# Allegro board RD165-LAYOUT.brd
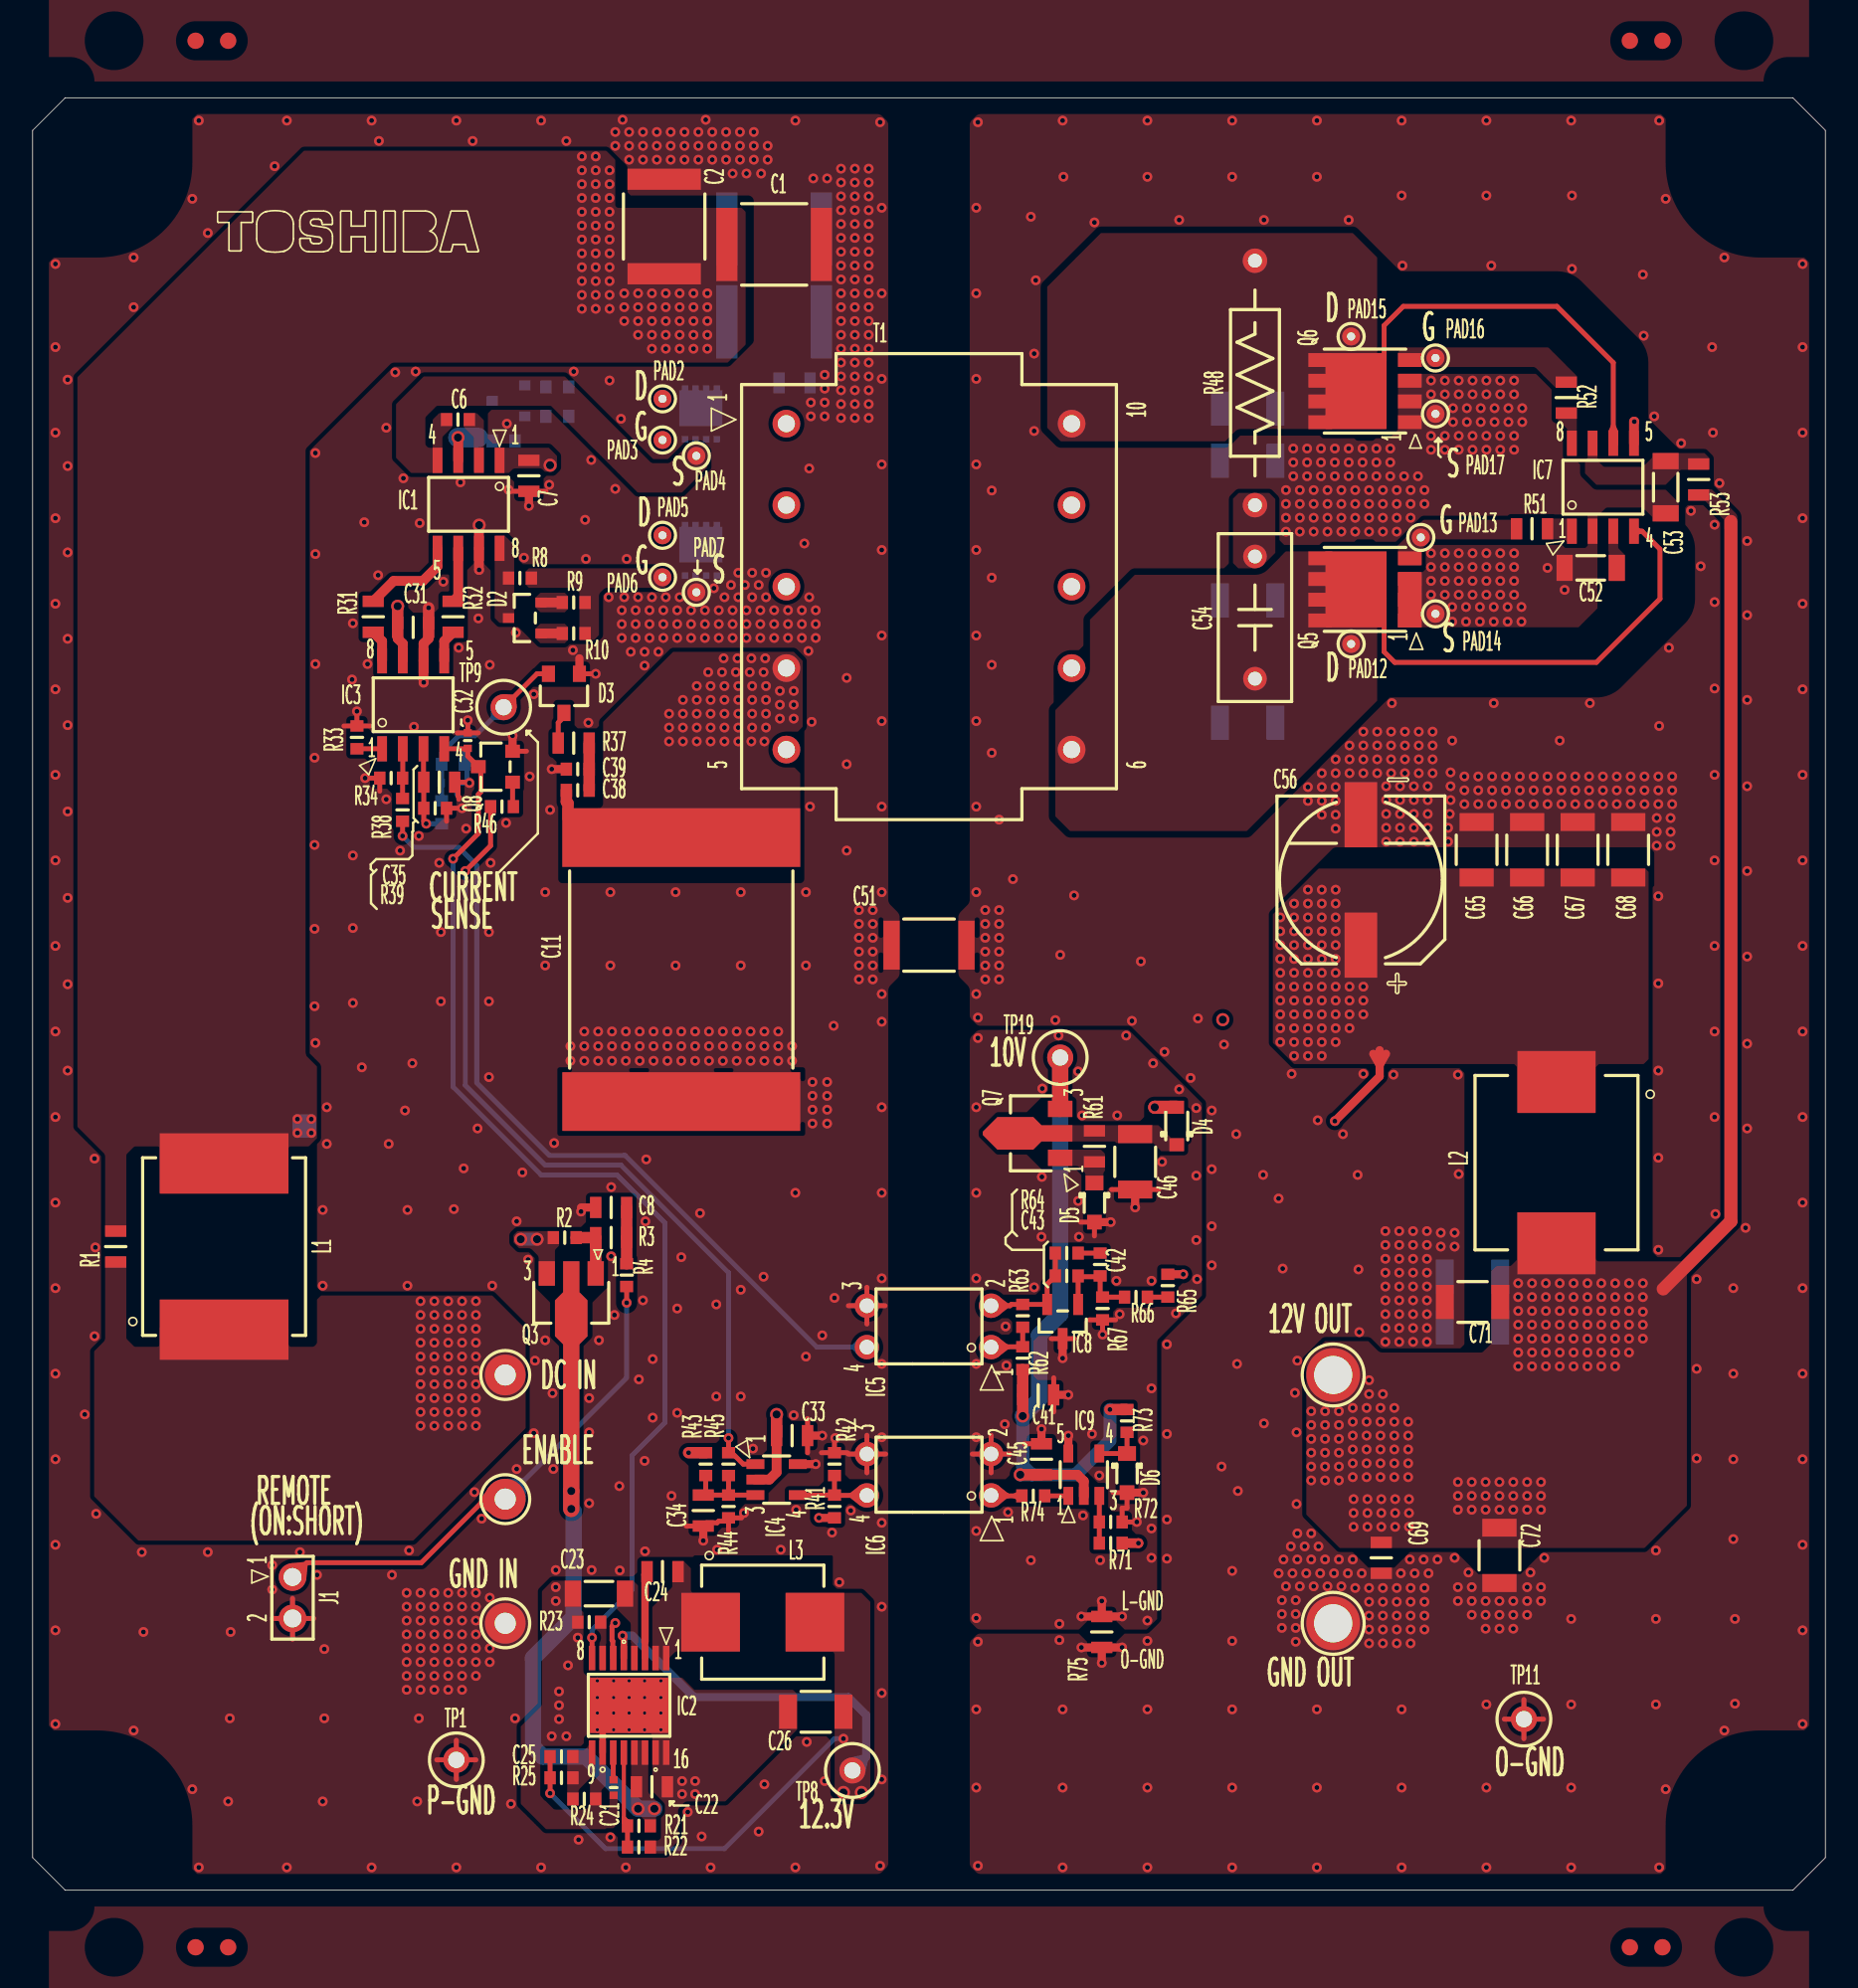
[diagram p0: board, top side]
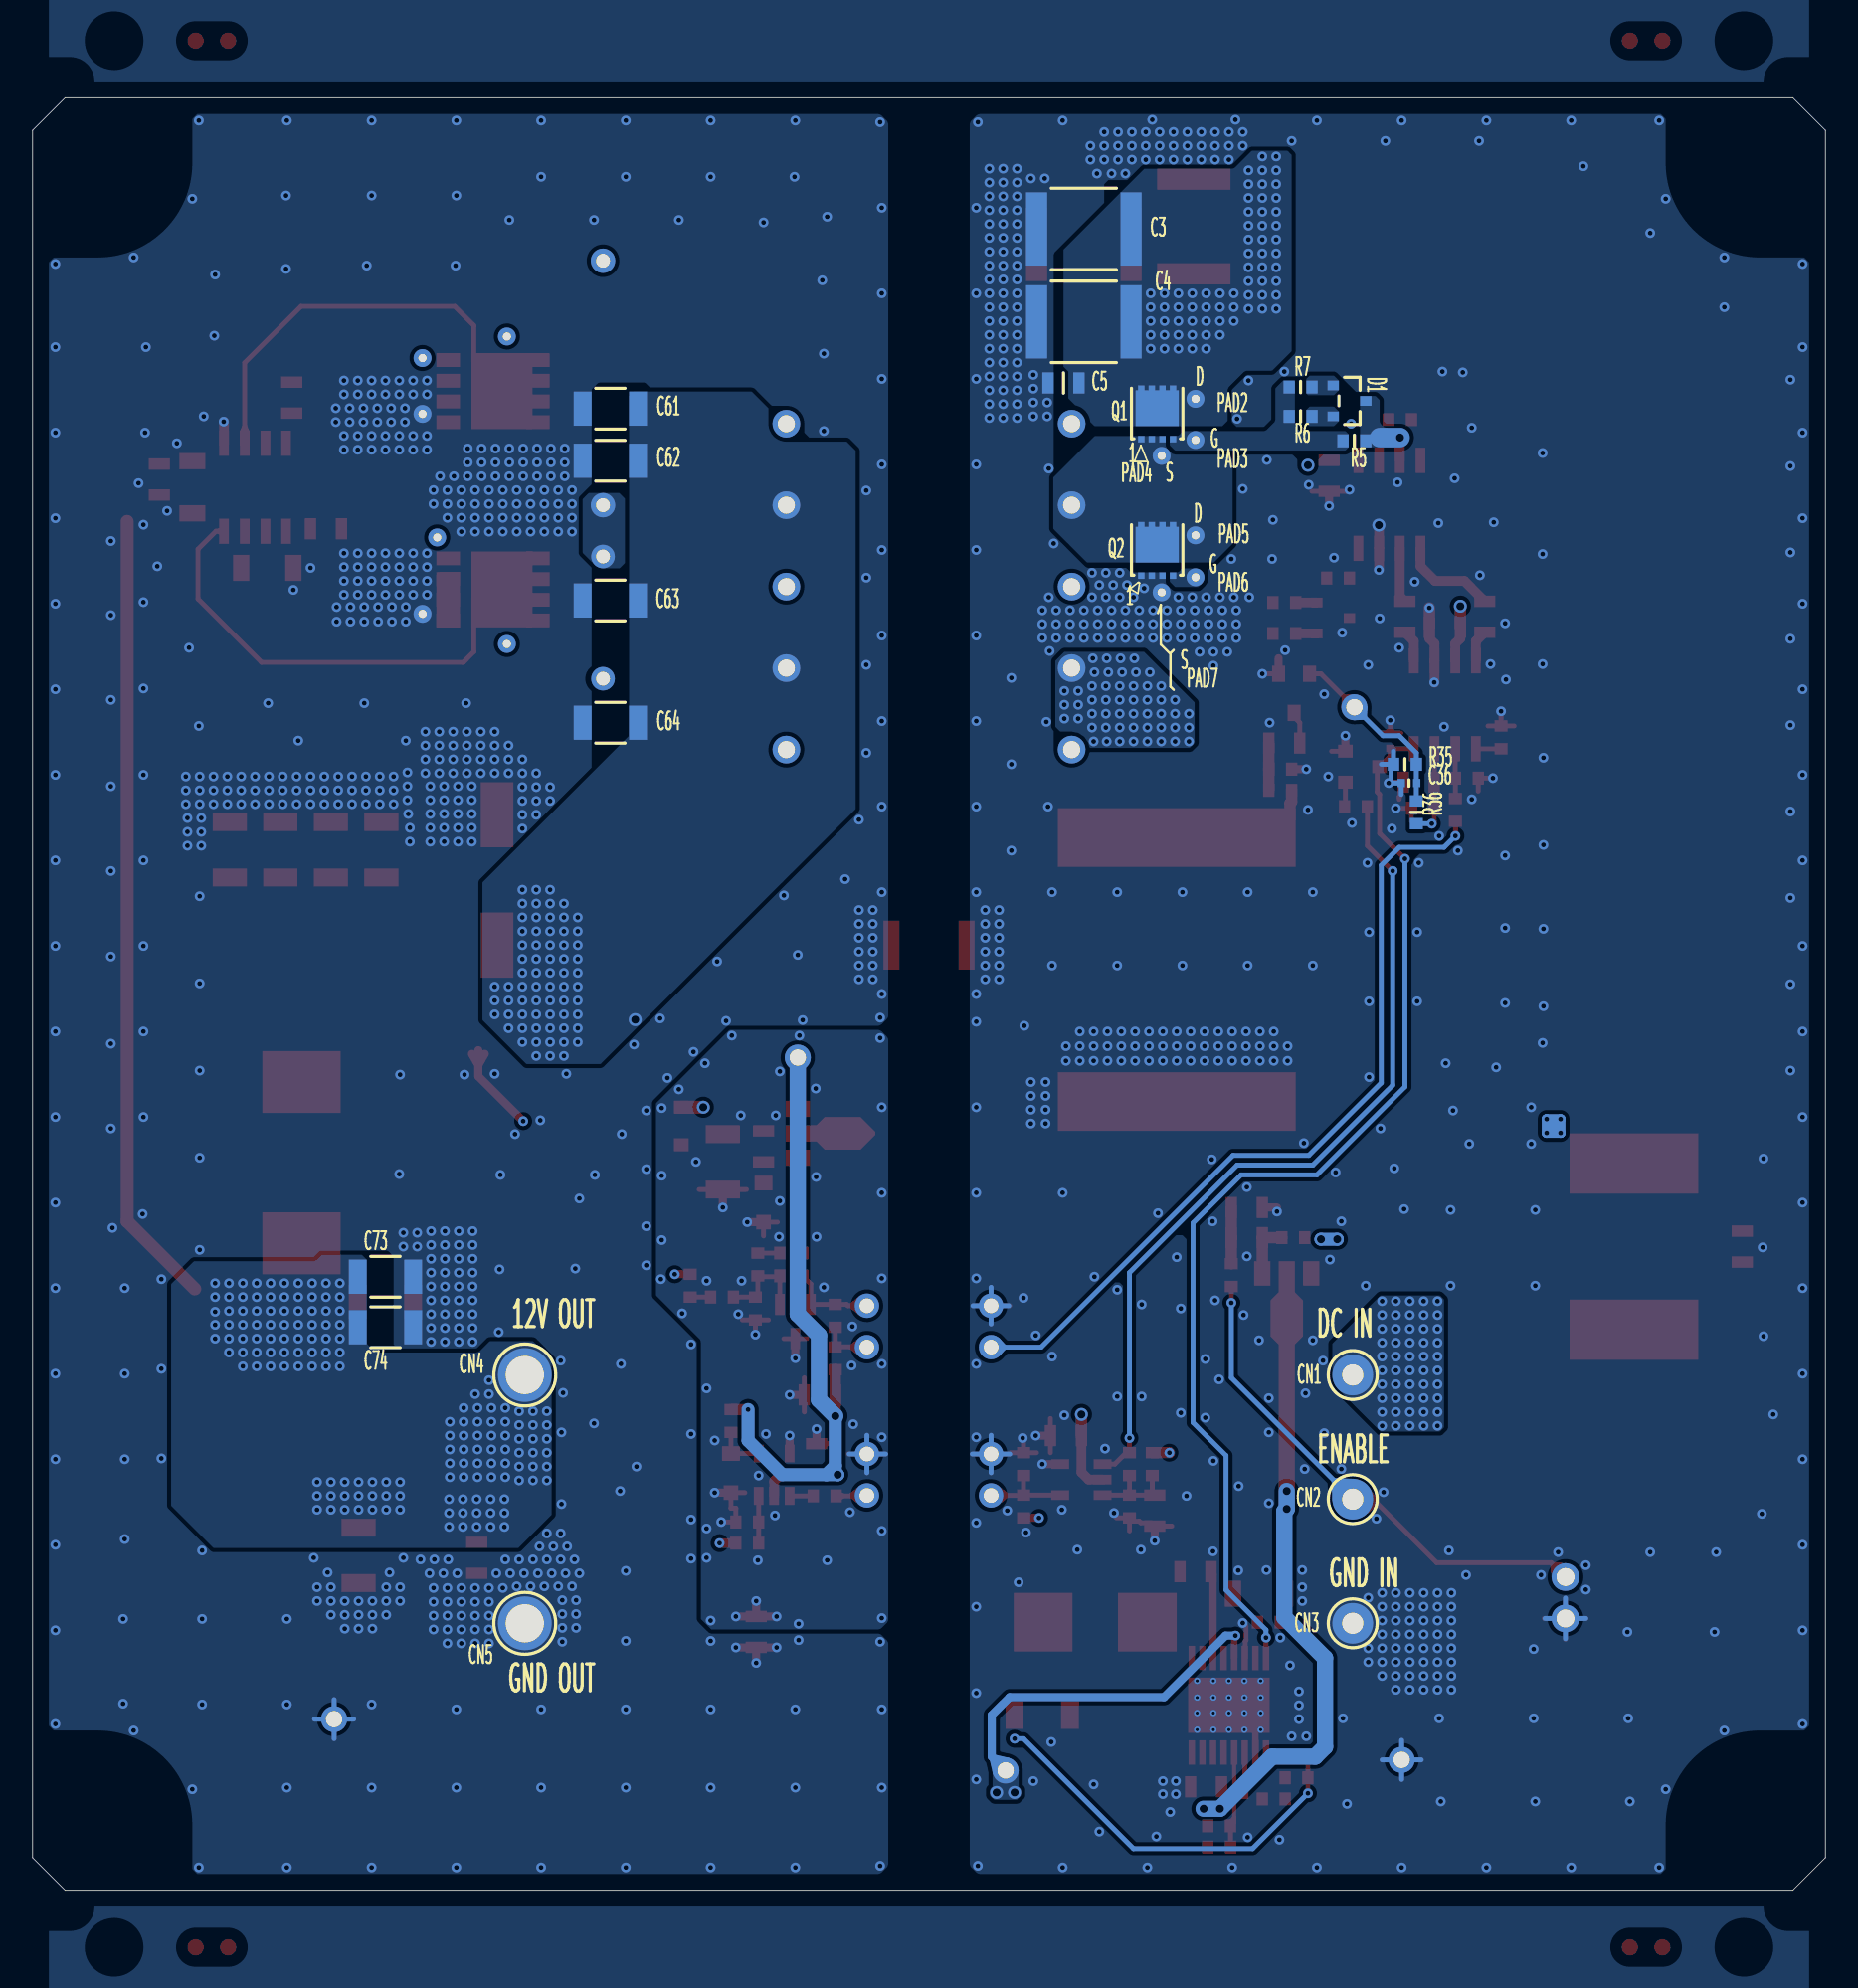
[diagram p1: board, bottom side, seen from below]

Outline 110 x 110 mm; copper layers: TOP, CONDUCTIVE2, CONDUCTIVE3, BOTTOM. Coordinates in mm from the lower left corner of the outline.
Outline path: 0,108 2,110 108,110 110,108 110,2 108,0 2,0 0,2 0,108

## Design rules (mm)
constraint set DEFAULT: 

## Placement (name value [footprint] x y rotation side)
C1  -  [CHIP5750_TD]  45.5 101 0 top
C2  -  [CHIP5750_TD]  38.75 102.1 90 top
C3  -  [CHIP5750_TD]  45.5 101.95 0 bottom
C4  -  [CHIP5750_TD]  45.5 96.25 0 bottom
C5  -  [CHIP2012_GS_1]  46.75 92.5 0 bottom
C6  -  [CHIP1608_GS_1]  26.1 90.25 0 top
C7  -  [CHIP2012_GS_1]  30.45 86.8 90 top
C8  -  [CHIP2012_GS_1]  35.5 41.9 180 top
C11  -  [C_S_CB182E0475__AV]  39.8 56.5 270 top
C21  -  [CHIP1005_GS_2]  35.65 6.3 90 top
C22  -  [CHIP2012_GS_1]  38 6.35 0 top
C23  -  [CHIP3216_GS_1]  34.75 18.2 180 top
C24  -  [CHIP2012_GS_1]  38.65 19.55 0 top
C25  -  [CHIP1608_GS_1]  32.45 8.2 180 top
C26  -  [CHIP3225_GS]  48.05 10.95 180 top
C31  -  [CHIP2012_GS_1]  23.35 77.5 0 top
C32  -  [CHIP1005_GS_2]  26.7 70.55 270 top
C33  -  [CHIP2012_GS_1]  46.6 27.9 0 top
C34  -  [CHIP2012_GS_1]  41.15 23.3 270 top
C35  -  [CHIP2012_GS_1]  24.95 68 0 top
C36  -  [CHIP1005_GS_2]  25.55 67.95 0 bottom
C38  -  [CHIP1608_GS_1]  33.45 67.5 180 top
C39  -  [CHIP1608_GS_1]  33.45 68.8 180 top
C41  -  [CHIP2012_GS_1]  61.7 30.4 0 top
C42  -  [CHIP1608_GS_1]  65.5 38.4 270 top
C43  -  [CHIP1608_GS_1]  63.45 37.7 0 top
C45  -  [CHIP2012_GS_1]  61.9 26.45 270 top
C46  -  [CHIP3225_GS]  67.65 44.7 270 top
C51  -  [CHIP4632_AV]  55 58 0 top
C52  -  [CHIP3216_GS_1]  95.6 81.15 180 top
C53  -  [CHIP3216_GS_1]  100.2 86.1 270 top
C54  -  [C_I_ECQE2_3_F_PN]  75 78.1 90 top
C56  -  [AC_S_10X12_7L_NC_2]  81.5 62 0 top
C61  -  [CHIP3225_GS]  74.55 90.92 0 bottom
C62  -  [CHIP3225_GS]  74.55 87.72 0 bottom
C63  -  [CHIP3225_GS]  74.55 79.15 0 bottom
C64  -  [CHIP3225_GS]  74.55 71.65 0 bottom
C65  -  [CHIP3225_GS]  88.6 63.85 90 top
C66  -  [CHIP3225_GS]  91.7 63.85 90 top
C67  -  [CHIP3225_GS]  94.8 63.85 90 top
C68  -  [CHIP3225_GS]  97.9 63.85 90 top
C69  -  [CHIP2012_GS_1]  82.75 20.4 270 top
C71  -  [CHIP3225_GS]  88.35 36.1 180 top
C72  -  [CHIP3225_GS]  90 20.55 270 top
C73  -  [CHIP3225_GS]  88.35 37.65 180 bottom
C74  -  [CHIP3225_GS]  88.35 34.55 180 bottom
CN1  -  [TP_I_6834_0_00__00_0_1]  29 31.62 90 bottom
CN2  -  [TP_I_6834_0_00__00_0_1]  29 24 270 bottom
CN3  -  [TP_I_6834_0_00__00_0_1]  29 16.38 270 bottom
CN4  -  [TP_I_8237_0_05__00_0_1]  79.8 31.62 180 bottom
CN5  -  [TP_I_8237_0_05__00_0_1]  79.8 16.38 180 bottom
D1  -  [DI_S_SOT23_3_0_95_TS]  29.2 91.4 270 bottom
D2  -  [DI_S_SOT23_3_0_95_TS]  30.2 78.08 90 top
D3  -  [DI_S_1SS226_TS]  32.6 73.45 180 top
D4  -  [DI_S_SOD323_2_TS_A]  70.2 46.9 90 top
D5  -  [DI_S_SC90A_2_PN_A]  65.15 42.2 270 top
D6  -  [DI_S_SC90A_2_PN_A]  67.15 25.6 270 top
IC1  -  [IC_S_SOP_8_1_27_TI]  26.75 85.05 180 top
IC2  -  [IC_S_SOP_16E_0_65_GS]  36.6 11.35 180 top
IC3  -  [IC_S_SOP_8_1_27_TI]  23.35 72.75 0 top
IC4  -  [IC_S_SOT23_5_0_95_TI]  45.65 25.2 270 top
IC5  -  [PH_I_TLP785_TS_1]  55 34.6 90 top
IC6  -  [PH_I_TLP785_TS_1]  55 25.5 90 top
IC7  -  [IC_S_SOP_8_1_27_TI]  96.35 86.1 0 top
IC8  -  [IC_S_SOT23_3_0_95_TI]  63.2 34.9 180 top
IC9  -  [IC_S_SOT23_5_0_95_TI]  64.5 25.5 0 top
J1  -  [HP_I_FFC_2AMEP1_HN]  15.95 17.95 270 top
L1  -  [L_S_ETQP5M__YLC_PN]  11.75 39.5 270 top
L2  -  [L_S_ETQP5M__YFC_PN]  93.5 44.65 90 top
L3  -  [L_S_ETQP5M__Y_M_PN]  44.8 16.45 180 top
NOREF  -  []  106 4 0 top
NOREF#2  -  []  105 113.5 0 top
NOREF#3  -  []  4 106 0 top
NOREF#4  -  [unnamed#2]  100 113.5 180 top
NOREF#5  -  [unnamed#2]  10 113.5 0 top
NOREF#6  -  []  10.55 98.3 0 top
NOREF#7  -  [unnamed#2]  10 -3.5 0 top
NOREF#8  -  []  105 -3.5 0 top
NOREF#9  -  []  -5 -30 0 top
NOREF#10  -  []  5 -3.5 0 top
NOREF#11  -  []  5 113.5 0 top
NOREF#12  -  []  4 4 0 top
NOREF#13  -  []  106 106 0 top
NOREF#14  -  [unnamed#2]  100 -3.5 180 top
NOREF#15  -  []  -5 -35 0 top
PAD2  -  [TP_I_TH0_5_LC1_1_RC1_1]  38.65 91.53 0 top
PAD3  -  [TP_I_TH0_5_LC1_1_RC1_1]  38.65 89 0 top
PAD4  -  [TP_I_TH0_5_LC1_1_RC1_1]  40.73 88.03 0 top
PAD5  -  [TP_I_TH0_5_LC1_1_RC1_1]  38.65 83.15 0 top
PAD6  -  [TP_I_TH0_5_LC1_1_RC1_1]  38.65 80.58 0 top
PAD7  -  [TP_I_TH0_5_LC1_1_RC1_1]  40.73 79.65 0 top
PAD12  -  [TP_I_TH0_5_LC1_1_RC1_1]  80.9 76.48 0 top
PAD13  -  [TP_I_TH0_5_LC1_1_RC1_1]  85.17 83.02 0 top
PAD14  -  [TP_I_TH0_5_LC1_1_RC1_1]  86.08 78.33 0 top
PAD15  -  [TP_I_TH0_5_LC1_1_RC1_1]  80.9 95.35 0 top
PAD16  -  [TP_I_TH0_5_LC1_1_RC1_1]  86.08 94.03 0 top
PAD17  -  [TP_I_TH0_5_LC1_1_RC1_1]  86.08 90.6 0 top
Q1  -  [TR_S_SON_ADVANCE_TS__1]  41 90.62 180 bottom
Q2  -  [TR_S_SON_ADVANCE_TS__1]  41 82.25 180 bottom
Q3  -  [TR_S_SC62_3_1_5_TS]  33.05 36.05 180 top
Q5  -  [TR_S_SOP_ADVANCE_TS__1]  81.75 79.83 90 top
Q6  -  [TR_S_SOP_ADVANCE_TS__1]  81.75 92 90 top
Q7  -  [TR_S_SC62_3_1_5_TS]  61.25 46.45 90 top
Q8  -  [TR_S_SOT23F_3_0_95_T_1]  28.4 68.95 90 top
R1  -  [CHIP2012_GS_1]  5.1 39.5 270 top
R2  -  [CHIP1608_GS_1]  32.65 40.05 0 top
R3  -  [CHIP2012_GS_1]  35.5 40.05 180 top
R4  -  [CHIP1608_GS_1]  36.45 37.75 90 top
R5  -  [CHIP1608_GS_1]  28.9 88.95 0 bottom
R6  -  [CHIP1608_GS_1]  32.2 90.45 0 bottom
R7  -  [CHIP1608_GS_1]  32.2 92.25 0 bottom
R8  -  [CHIP1608_GS_1]  29.9 80.53 0 top
R9  -  [CHIP1608_GS_1]  33.2 79.03 0 top
R10  -  [CHIP1608_GS_1]  33.2 77.12 0 top
R21  -  [CHIP1608_GS_1]  37.2 3.95 180 top
R22  -  [CHIP1608_GS_1]  37.2 2.65 0 top
R23  -  [CHIP1608_GS_1]  34.15 16.45 180 top
R24  -  [CHIP1608_GS_1]  33.85 5.6 180 top
R25  -  [CHIP1608_GS_1]  32.45 6.9 180 top
R31  -  [CHIP2012_GS_1]  20.9 78.15 270 top
R32  -  [CHIP2012_GS_1]  25.8 78.15 270 top
R33  -  [CHIP1608_GS_1]  19.9 70.75 90 top
R34  -  [CHIP1608_GS_1]  22 68.25 180 top
R35  -  [CHIP1608_GS_1]  25.8 69.1 180 bottom
R36  -  [CHIP1608_GS_1]  25.1 66.15 270 bottom
R37  -  [CHIP2012_GS_1]  33.2 70.4 180 top
R38  -  [CHIP1608_GS_1]  22.7 66.3 270 top
R39  -  [CHIP1608_GS_1]  24.7 66.4 180 top
R41  -  [CHIP1608_GS_1]  49.2 23.55 270 top
R42  -  [CHIP1608_GS_1]  49.2 26.15 270 top
R43  -  [CHIP1608_GS_1]  41.3 26.15 90 top
R44  -  [CHIP1608_GS_1]  42.7 23.55 90 top
R45  -  [CHIP1608_GS_1]  42.7 26.15 270 top
R46  -  [CHIP1608_GS_1]  28.8 66.5 180 top
R48  -  [R_I_MOS1C_GS_1]  75 92.5 270 top
R51  -  [CHIP2012_GS_1]  92 83.55 0 top
R52  -  [CHIP2012_GS_1]  94.1 91.6 90 top
R53  -  [CHIP2012_GS_1]  102.22 86.58 90 top
R61  -  [CHIP2012_GS_1]  65.15 45.65 270 top
R62  -  [CHIP1608_GS_1]  60.75 32.65 270 top
R63  -  [CHIP1608_GS_1]  60.75 35.25 270 top
R64  -  [CHIP1608_GS_1]  63.45 39.1 180 top
R65  -  [CHIP1608_GS_1]  69.65 37.1 270 top
R66  -  [CHIP1608_GS_1]  67.7 36.4 180 top
R67  -  [CHIP1608_GS_1]  65.65 35.7 90 top
R71  -  [CHIP1608_GS_1]  66.15 21.3 180 top
R72  -  [CHIP1608_GS_1]  66.15 22.6 180 top
R73  -  [CHIP1608_GS_1]  67.15 28.8 90 top
R74  -  [CHIP1608_GS_1]  61.4 24.2 0 top
R75  -  [CHIP2012_GS_1]  65.6 15.85 90 top
T1  -  [T_I_PC40EER28_GS]  55 80 270 top
TP1  -  [TP_I_LC_22_GS]  26 8 0 top
TP8  -  [TP_I_LC_22_GS]  50.3 7.35 270 top
TP9  -  [TP_I_LC_22_GS]  28.9 72.6 90 top
TP11  -  [TP_I_LC_22_GS]  91.5 10.5 0 top
TP19  -  [TP_I_LC_22_GS]  63.05 51.1 270 top

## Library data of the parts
C1-C4 = Chip5750_TD: alternate symbols: (T:Chip5750_TD;B:Chip5750_TD,C4_Chip5750_TD)
C5 C7 C8 C22 C24 C31 C33-C35 C41 C45 C69 R1 R3 R31 R32 R37 R51-R53 R61 R75 = Chip2012_GS_1: alternate symbols: (T:Chip2012_GS_1;B:Chip2012_GS_1,C5_Chip2012_GS_1)
C6 C25 C38 C39 C42 C43 R2 R4-R10 R21-R25 R33-R36 R38 R39 R41-R46 R62-R67 R71-R74 = Chip1608_GS_1: alternate symbols: (T:Chip1608_GS_1;B:Chip1608_GS_1,R6_Chip1608_GS_1)
C11 = CB182E0475***_AV
C21 C32 C36 = Chip1005_GS_2
C23 C52 C53 = Chip3216_GS_1
C26 C46 C61-C68 C71-C74 = Chip3225_GS: alternate symbols: (T:Chip3225_GS;B:Chip3225_GS,C63_Chip3225_GS,C64_Chip3225_GS,C74_Chip3225_GS)
C51 = Chip4632_AV
C54 = ECQE2**3*F_PN
C56 = PCR1****MCL1GS_NC
CN1-CN3 = 6834-0-00-**-00-00-03-0_ML
CN4 CN5 = 8237-0-05-**-00-00-03-0_ML
D1 D2 = TBAT54S_TS: alternate symbols: (T:DI_S_SOT23_3_0_95_TS;B:DI_S_SOT23_3_0_95_TS,D1_DI_S_SOT23_3_0_95_1)
D3 = 1SS226_TS
D4 = BAS316_TS_A
D5 = DZ2J110M0L_PN_A
D6 = DZ2J056*0L_PN_A
IC1 = UCC272**AD_TI
IC2 = LM46000PWP_GS
IC3 = UCC25600D*_TI
IC4 IC9 = TLV7211AIDBVR_TI
IC5 IC6 = TLP785_TS_1
IC7 = UCC24624D*_TI
IC8 = TLVH43***DBZ*_TI
J1 = FFC-2AMEP1_HN
L1 = ETQP5M***YLC_PN
L2 = ETQP5M***YFC_PN
L3 = ETQP5M***Y*M_PN
PAD2-PAD7 PAD12-PAD17 = TP_I_TH0.5_LC1.1_RC1.2_GS: alternate symbols: (PAD4_TP_I_TH0_5_LC1__1)
Q1 Q2 = TPN7R504PL_TS_A: alternate symbols: (T:TR_S_SON_ADVANCE_TS__1;B:TR_S_SON_ADVANCE_TS__1,Q1_TR_S_SON_ADVANCE__1)
Q3 = 2SA2070_TS
Q5 Q6 = TPH1R204PL_TS_A: alternate symbols: (Q5_TR_S_SOP_ADVANCE__1)
Q7 = 2SC5810_TS
Q8 = SSM3K339R_TS_A
R48 = MOS1C****_GS_1
T1 = PC40EER28_GS
TP1 TP8 TP9 TP11 TP19 = LC-22_GS

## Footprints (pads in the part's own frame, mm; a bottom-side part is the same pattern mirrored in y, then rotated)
AC_S_10X12_7L_NC_2
  rect 2x4 smd: 1(0,-4) 2(0,4)
C_I_ECQE2_3_F_PN
  round 1.45 hole 0.85: 1(-3.75,0) 2(3.75,0)
C_S_CB182E0475__AV
  custom 0.9x0.9 smd: 1(-8.1,0) 2(8.1,0)
CHIP1005_GS_2
  rect 0.45x0.5 smd: 1(-0.475,0) 2(0.475,0)
CHIP1608_GS_1
  rect 0.7x0.8 smd: 1(-0.7,0) 2(0.7,0)
CHIP2012_GS_1
  rect 0.7x1.3 smd: 1(-0.95,0) 2(0.95,0)
CHIP3216_GS_1
  rect 1x1.6 smd: 1(-1.6,0) 2(1.6,0)
CHIP3225_GS
  rect 1.1x2.1 smd: 1(-1.7,0) 2(1.7,0)
CHIP4632_AV
  rect 1x3 smd: 1(-2.3,0) 2(2.3,0)
CHIP5750_TD
  rect 1.3x4.5 smd: 1(-2.9,0) 2(2.9,0)
DI_S_1SS226_TS
  rect 0.8x1 smd: 1(-0.95,-1.2) 2(0.95,-1.2) 3(0,1.2)
DI_S_SC90A_2_PN_A
  rect 0.9x0.9 smd: 1(1.2,0)
  rect 0.9x1.1 smd: 2(-1.2,0)
DI_S_SOD323_2_TS_A
  rect 0.8x0.9 smd: 1(1.15,0) 2(-1.15,0)
DI_S_SOT23_3_0_95_TS
  rect 0.6x0.7 smd: 1(-0.95,-1) 2(0.95,-1) 3(0,1)
HP_I_FFC_2AMEP1_HN
  round 1.7 hole 1.1: 1(-1.27,0) 2(1.27,0)
IC_S_SOP_8_1_27_TI
  rect 0.6x1.55 smd: 1(-1.905,-2.7) 2(-0.635,-2.7) 3(0.635,-2.7) 4(1.905,-2.7) 5(1.905,2.7) 6(0.635,2.7) 7(-0.635,2.7) 8(-1.905,2.7)
IC_S_SOP_16E_0_65_GS
  rect 0.4x1.5 smd: 1(-2.275,-2.9) 2(-1.625,-2.9) 3(-0.975,-2.9) 4(-0.325,-2.9) 5(0.325,-2.9) 6(0.975,-2.9) 7(1.625,-2.9) 8(2.275,-2.9) 9(2.275,2.9) 10(1.625,2.9) 11(0.975,2.9) 12(0.325,2.9) 13(-0.325,2.9) 14(-0.975,2.9) 15(-1.625,2.9) 16(-2.275,2.9)
  custom 0.85x0.85 smd: EP(0,0)
IC_S_SOT23_3_0_95_TI
  rect 0.6x1.3 smd: 1(-0.95,-1.05) 2(0.95,-1.05) 3(0,1.05)
IC_S_SOT23_5_0_95_TI
  rect 0.6x1.1 smd: 1(-0.95,-1.3) 2(0,-1.3) 3(0.95,-1.3) 4(0.95,1.3) 5(-0.95,1.3)
L_S_ETQP5M__Y_M_PN
  rect 3.6x3.6 smd: 1(3.2,0) 2(-3.2,0)
L_S_ETQP5M__YFC_PN
  rect 3.8x4.8 smd: 1(4.95,0) 2(-4.95,0)
L_S_ETQP5M__YLC_PN
  custom 0.925x0.925 smd: 1(5.1,0) 2(-5.1,0)
PH_I_TLP785_TS_1
  round 1.5 hole 0.9: 1(-1.27,-3.81) 2(1.27,-3.81) 3(1.27,3.81) 4(-1.27,3.81)
R_I_MOS1C_GS_1
  round 1.5 hole 0.85: 1(-7.5,0) 2(7.5,0)
T_I_PC40EER28_GS
  round 1.7 hole 1.05: 1(-10,-8.75) 2(-5,-8.75) 3(0,-8.75) 4(5,-8.75) 5(10,-8.75) 6(10,8.75) 7(5,8.75) 8(0,8.75) 9(-5,8.75) 10(-10,8.75)
TP_I_6834_0_00__00_0_1
  round 2.5 hole 1.3: 1(0,0)
TP_I_8237_0_05__00_0_1
  round 3.3 hole 2.34: 1(0,0)
TP_I_LC_22_GS
  round 1.6 hole 1: 1(0,0)
TP_I_TH0_5_LC1_1_RC1_1
  round 1.1 hole 0.5: 1(0,0)
TR_S_SC62_3_1_5_TS
  rect 1x1.5 smd: 1(-1.5,-1.8) 3(1.5,-1.8)
  custom 0.5x0.5 smd: 2(0,0.2)
TR_S_SON_ADVANCE_TS__1
  rect 0.4x0.4 smd: (-0.975,-1.575) (-0.975,1.525) (-0.325,1.525) (0.325,-1.575) (0.325,1.525) (0.975,1.525) G(0.975,-1.575) S(-0.325,-1.575)
  custom 0.55x0.55 smd: D(0,0.325)
TR_S_SOP_ADVANCE_TS__1
  rect 0.85x1.45 smd: (-1.905,2.75) (-1.905,-2.75) (-0.635,2.75) (0.635,2.75) (0.635,-2.75) (1.905,2.75) G(1.905,-2.75) S(-0.635,-2.75)
  custom 0.938x0.938 smd: D(0,0.55)
TR_S_SOT23F_3_0_95_T_1
  rect 0.8x0.9 smd: D(0,1.05) G(-0.95,-1.05) S(0.95,-1.05)
unnamed#2
  round 1 smd: (0,0) (2,0)

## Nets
12V: C7.2 C25.2 C26.1(TP-1) C31.1(TP-1) C33.1(TP-1) IC1.1 IC2.5 IC3.7 IC4.2 L3.2 R25.2 R41.2 R43.2 TP8.1
L_GND: C41.2 C45.1(TP-1) C46.2 D5.1(TP-1) D6.1(TP-1) IC6.2 IC8.3 IC9.5 R67.1(TP-1) R72.1(TP-1) R75.2
O_GND: C51.2 C52.2 C53.2 C56.2 C61.2 C62.2 C63.2 C64.2 C65.2 C66.2 C67.2 C68.2 C69.2 C71.2 C72.2 C73.2 C74.2 CN5.1 IC7.2 IC7.5 PAD14.1 PAD17.1 Q5.S Q6.S R75.1(TP-1) TP11.1
P-GND: C1.2 C2.2 C3.2 C4.2 C5.2 C7.1(TP-1) C8.2 C11.2 C21.1(TP-1) C22.2 C23.2 C26.2 C31.2 C32.1(TP-1) C33.2 C34.2 C35.2 C36.2 C39.2 C51.1(TP-1) CN3.1 D3.1 IC1.7 IC2.6 IC2.10 IC2.15 IC2.16 IC2.EP IC3.6 IC4.5 IC5.3 IC6.3 J1.2 PAD7.1 Q2.S Q8.S R22.2 R23.2 R24.1(TP-1) R33.2 R34.2 R35.1(TP-1) R39.1(TP-1) R42.1(TP-1) R44.1(TP-1) TP1.1
VOUT: C69.1(TP-1) C71.1(TP-1) C72.1(TP-1) C73.1(TP-1) C74.1(TP-1) CN4.1 L2.2 R53.1(TP-1) R71.1(TP-1)
VSEC: C56.1(TP-1) C61.1(TP-1) C62.1(TP-1) C63.1(TP-1) C64.1(TP-1) C65.1(TP-1) C66.1(TP-1) C67.1(TP-1) C68.1(TP-1) D4.1(TP-1) L2.1(TP-1) R65.1(TP-1) T1.7 T1.9
N04422: C1.1(TP-1) C2.1(TP-1) C3.1(TP-1) C4.1(TP-1) C5.1(TP-1) L1.2 PAD2.1 Q1.D Q3.3 R1.1(TP-1) R2.1(TP-1)
N07028: PAD3.1 Q1.G R5.2 R6.2 R7.2
N07195: PAD6.1 Q2.G R8.2 R9.2 R10.2
N07250: D1.3 IC1.3 R5.1(TP-1)
N07459: D2.3 IC1.8 R8.1(TP-1)
N07528: C6.1(TP-1) IC1.4 PAD4.1 PAD5.1 Q1.S Q2.D T1.2
N08453: CN1.1 L1.1(TP-1) R1.2
N17255: PAD16.1 Q6.G R52.2
N17449: IC7.6 PAD15.1 Q6.D R48.1(TP-1) T1.10
N20934: C54.1(TP-1) IC7.4 PAD12.1 Q5.D T1.6
N27715: C54.2 R48.2
N75033: D1.1 R7.1(TP-1)
N75062: D1.2 R6.1(TP-1)
N76065: D2.1 R10.1(TP-1)
N76205: D2.2 R9.1(TP-1)
N140316: C6.2 IC1.2
N143092: C22.1(TP-1) IC2.13 IC2.14 Q3.2 R21.1(TP-1)
N143611: C25.1(TP-1) IC2.9 R24.2 R25.1(TP-1)
N146449: C21.2 IC2.11
N147050: C24.2 IC2.1 IC2.2 L3.1(TP-1)
N147270: C24.1(TP-1) IC2.3
N147478: C23.1(TP-1) IC2.4
N147857: IC2.7 R23.1(TP-1)
N147939: C32.2 IC2.8 IC3.4 Q8.D
N154702: IC2.12 R21.2 R22.1(TP-1)
N156453: IC3.8 R31.2
N156506: IC3.5 R32.2
N157128: IC3.1 R33.1(TP-1)
N157174: IC3.2 R34.1(TP-1) R38.1(TP-1)
N157213: C35.1(TP-1) IC3.3 R36.2 R39.2
N161036: PAD13.1 Q5.G R51.1(TP-1)
N161438: IC7.8 R52.1(TP-1)
N162279: C53.1(TP-1) IC7.7 R53.2
N162488: C52.1(TP-1) IC7.3
N170235: IC7.1 R51.2
N179665: IC1.6 R32.1(TP-1)
N179711: IC1.5 R31.1(TP-1)
N180947: IC5.4 R38.2
N181356: C11.1(TP-1) C38.2 T1.4
N183929: IC4.1 R45.1(TP-1) R46.2
N185355: IC4.4 IC6.4 R41.1(TP-1) R42.2
N185580: C34.1(TP-1) IC4.3 R43.1(TP-1) R44.2 R45.2
N188391: IC9.3 R71.2 R72.2
N188419: C41.1(TP-1) C45.2 IC9.2 Q7.3 R62.2 R73.2 TP19.1
N188459: D6.2 IC9.4 R73.1(TP-1)
N188511: IC9.1 R74.2
N193009: IC6.1 R74.1(TP-1)
N193836: C46.1(TP-1) D4.2 Q7.2 R61.1(TP-1)
N194076: D5.2 Q7.1 R61.2
N197110: C43.1(TP-1) IC5.2 IC8.2 R63.1(TP-1) R64.2
N197426: IC5.1 R62.1(TP-1) R63.2
N197850: R65.2 R66.1(TP-1)
N197854: C42.2 C43.2 IC8.1 R66.2 R67.2
N198958: C42.1(TP-1) R64.1(TP-1)
N206320: C38.1(TP-1) C39.1(TP-1) R37.1(TP-1)
N207190: D3.3 R37.2
N207547: C36.1(TP-1) D3.2 R35.2 R36.1(TP-1) TP9.1
N216469: Q3.1 R2.2 R3.2
N216829: C8.1(TP-1) R3.1(TP-1) R4.2
N216837: CN2.1 J1.1(TP-1) R4.1(TP-1)
N219686: Q8.G R46.1(TP-1)

Pads without a net: T1 1 3 5 8

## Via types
v1: diameter 0.6, hole 0.3, TOP to BOTTOM, 1631 vias
v2: diameter 0.8, hole 0.5, TOP to BOTTOM, 17 vias
v3: diameter 0.4, hole 0.2, TOP to BOTTOM, 20 vias

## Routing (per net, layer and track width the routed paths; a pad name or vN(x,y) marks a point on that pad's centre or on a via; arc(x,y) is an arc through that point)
12V: length 134.5
  TOP w0.3: C25.2 R25.2 v1(31.75,5.95)
  TOP w0.4: IC2.5 36.27,15.55 v1(36.2,15.62)
  TOP w0.5: v1(48.25,22.85) R41.2
  TOP w0.6: C31.1 22.4,76.81 22.71,76.5 22.71,75.5 ; C33.1 45.65,25.65 45.2,25.2 IC4.2
  TOP w0.7: R43.2 v1(40.25,26.85) ; C33.1 v2(45.65,29.2) ; C31.1 v2(22.4,78.8)
  CONDUCTIVE3 w1.2: v2(31.75,87.45) 29,87.45 22.4,80.85 v2(22.4,78.8) 18.45,74.85 18.45,53.95 29.55,42.85 34.15,42.85 40.75,36.25 40.75,29.1
  BOTTOM w0.3: v1(31.75,5.95) 35.15,2.55 42.45,2.55 49.2,9.3 v1(49.75,9.3)
  BOTTOM w0.5: v1(36.2,15.62) 36.8,15.62 40.58,11.85 50.05,11.85 51.15,10.75 51.15,8.2 TP8.1
  vias: v2(49.75,6) v2(50.85,6)
L_GND: length 44.1
  TOP w0.3: 62.65,29.35 C41.2 62.65,31.45 ; 64.3,41 D5.1 65.15,40.15 ; C45.1 60.85,27.4 ; R67.1 64.85,35 ; R67.1 v1(65.65,34.1) ; R67.1 66.45,35 ; 69.1,43 C46.2 66.2,43 ; 66.3,24.4 D6.1 67.15,23.45 66.85,23.45 R72.1 v1(67.75,22.6) ; 62.5,33.85 IC8.3 63.9,33.85 ; IC6.2 58.81,27.92 ; IC6.2 59.96,26.77 ; IC6.2 57.66,26.77 ; IC6.2 58.81,25.62
  TOP w0.5: R75.2 64.45,16.8 ; R75.2 65.6,17.6 ; R75.2 66.7,16.8 ; v1(68.15,24.4) D6.1 ; v1(63.2,32.65) IC8.3 ; v1(63.55,30.4) C41.2 62.6,30.4 ; C46.2 v1(67.65,41.9) ; v1(61.9,28.3) C45.1 ; D5.1 v1(66.15,41) ; IC9.5 v1(63.55,27.9)
  CONDUCTIVE2 w0.3: IC6.2 58.81,25.62 ; IC6.2 59.96,26.77 ; IC6.2 57.66,26.77 ; IC6.2 58.81,27.92
  CONDUCTIVE3 w0.3: IC6.2 57.66,26.77 ; IC6.2 58.81,27.92 ; IC6.2 59.96,26.77 ; IC6.2 58.81,25.62
  BOTTOM w0.3: IC6.2 57.66,26.77 ; IC6.2 58.81,25.62 ; IC6.2 59.9,26.77 ; IC6.2 58.81,27.92
  vias: v1(57.9,48.05) v1(57.9,42.8) v1(57.9,37.55) v1(57.9,32.3) v1(57.9,27.8) v1(57.9,22.05) v1(57.9,16.7) v1(58,52.3) v1(59.65,28.6) v1(59.7,34.6) v1(59.75,32.2) v1(59.85,23.2) v1(61.25,20.25) v1(61.45,37) v1(61.92,43.77) v1(61.9,40.1) v1(61.95,49.2) v1(62.95,52.45) v1(63,16.35) v1(64.15,50.25) v1(64.15,42.3) v1(64.2,40.1) v1(64.35,16.8) v1(64.4,47.55) v1(64.45,23) v1(65,28) v1(65.45,25.45) v1(65.5,20.25) v1(65.6,17.75) v1(66.55,47.55) v1(66.5,37.4) v1(66.7,35.35) v1(66.85,16.8) v1(67.1,52.45) v1(68.15,27.6) v1(68.4,16.55) v1(68.65,37.4) v1(68.65,30.8) v1(68.65,22.2) v1(68.65,20.4) v1(68.75,50.75) v1(69.3,44.7) v1(70.15,35.4) v1(70.35,49.15) v1(71.4,48) v1(71.4,43.85) v1(71.4,39.9) v1(71.45,37.5)
O_GND: length 23.5
  TOP w0.3: TP11.1 91.5,9.3 ; TP11.1 91.5,11.7 ; TP11.1 92.7,10.5 ; TP11.1 90.3,10.5
  TOP w0.5: R75.1 64.5,14.9 ; R75.1 65.6,14.1 ; R75.1 66.7,14.9
  TOP w0.6: IC7.5 98.25,90.12
  CONDUCTIVE2 w0.3: TP11.1 92.7,10.5 ; TP11.1 90.3,10.5 ; TP11.1 91.5,9.3 ; TP11.1 91.5,11.7
  CONDUCTIVE3 w0.3: TP11.1 92.7,10.5 ; TP11.1 91.5,9.3 ; TP11.1 90.3,10.5 ; TP11.1 91.5,11.7
  BOTTOM w0.3: TP11.1 90.3,10.5 ; TP11.1 91.5,11.7 ; TP11.1 91.5,9.3 ; TP11.1 92.7,10.5
  vias: v1(57.9,103.25) v1(57.9,98) v1(57.9,92.75) v1(57.9,87.5) v1(57.9,82.25) v1(57.9,77) v1(57.9,71.75) v1(57.9,66.5) v1(57.9,61.25) v1(57.9,55) v1(57.9,11.1) v1(57.9,6.3) v1(58,108.5) v1(58,53.55) v1(58,15.25) v1(58,1.5) v1(58.45,60.15) v1(58.45,59.3) v1(58.45,58.45) v1(58.45,57.6) v1(58.45,56.75) v1(58.45,55.9) v1(58.85,85.9) v1(58.85,80.55) v1(58.85,75.2) v1(58.85,69.8) v1(59.3,65.7) v1(59.3,60.15) v1(59.3,59.3) v1(59.3,58.45) v1(59.3,57.6) v1(59.3,56.75) v1(59.3,55.9) v1(60.15,62.05) v1(61.25,102.7) v1(61.55,98.8) v1(61.45,94.3) v1(61.45,89.55) v1(62.75,53.4) v1(63.05,57.4) v1(63,15.35) v1(63.2,108.6) v1(63.25,105.15) v1(63.2,11.1) v1(63.2,6.3) v1(63.2,1.4) v1(63.9,61.05) v1(64.35,14.9) v1(65.15,102.35) v1(65.6,13.95) v1(66.85,14.9) v1(67.45,53.35) v1(68,57) v1(68.4,108.6) v1(68.4,105.15) v1(68.4,15.3) v1(68.4,11.1) v1(68.4,6.3) v1(68.4,1.4) v1(69.45,51.45) v1(69.6,33.5) v1(69.6,28) v1(69.6,22.75) v1(69.6,20.35) v1(70.35,102.5) v1(71.05,49.85) v1(71.5,53.5) v1(72.35,47.85) v1(72.35,44.25) v1(72.35,40.75) v1(72.35,38.35) v1(72.95,26) v1(73.1,51.9) v1(73.6,108.6) v1(73.6,105.15) v1(73.6,19.6) v1(73.6,15.3) v1(73.6,11.1) v1(73.6,6.3) v1(73.6,1.4) v1(73.85,46.4) v1(73.9,32.3) v1(73.95,24.5) v1(75.55,102.5) v1(75.5,43.9) v1(75.55,28.65) v1(76.45,42.45) v1(76.45,19.45) v1(76.7,38.15) v1(76.65,17.8) v1(76.65,16.95) v1(76.65,16.1) v1(76.75,20.3) v1(76.9,85.92) v1(76.9,85.08) v1(76.9,84.22) v1(76.9,83.38) v1(76.9,18.65) v1(77.25,50.1) v1(77.2,21.1) v1(77.35,88.47) v1(77.35,87.62) v1(77.35,86.78) v1(77.3,19.45) v1(77.45,30.52) v1(77.55,28.1) v1(77.55,23.7) v1(77.5,17.8) v1(77.5,16.95) v1(77.5,16.1) v1(77.5,15.25) v1(77.6,32.5) v1(77.6,21.9) v1(77.6,20.3) v1(77.75,85.92) v1(77.75,85.08) v1(77.75,84.22) v1(77.75,83.38) v1(77.75,18.65) v1(78.05,21.1) v1(78.2,88.47) v1(78.2,87.62) v1(78.2,86.78) v1(78.25,67.7) v1(78.25,66.85) v1(78.15,19.45) v1(78.45,21.9) v1(78.45,20.3) v1(78.6,85.92) v1(78.6,85.08) v1(78.6,84.22) v1(78.6,83.38) v1(78.6,18.65) v1(78.8,108.6) v1(78.8,105.15) v1(78.85,47.25) v1(78.8,11.1) v1(78.8,6.3) v1(78.8,1.4) v1(78.9,21.1) v1(79.05,88.47) v1(79.05,87.62) v1(79.05,86.78) v1(79,19.45) v1(79.1,68.55) v1(79.1,67.7) v1(79.1,66.85) v1(79.1,66) v1(79.3,20.3) v1(79.45,85.92) v1(79.45,85.08) v1(79.45,84.22) v1(79.45,83.38) v1(79.45,18.65) v1(79.85,19.45) v1(79.9,88.47) v1(79.9,87.62) v1(79.9,86.78) v1(79.95,69.4) v1(79.95,68.55) v1(79.95,67.7) v1(79.95,66.85) v1(79.95,66) v1(79.95,65.15) v1(80.15,20.3) v1(80.3,85.92) v1(80.3,85.08) v1(80.3,84.22) v1(80.3,83.38) v1(80.3,18.65) v1(80.4,46.4) v1(80.7,19.45) v1(80.75,102.5) v1(80.75,88.47) v1(80.75,87.62) v1(80.75,86.78) v1(80.8,70.25) v1(80.8,69.4) v1(80.8,68.55) v1(81,20.3) v1(81.15,85.92) v1(81.15,85.08) v1(81.15,84.22) v1(81.15,83.38) v1(81.15,18.55) v1(81.3,43.9) v1(81.35,38.1) v1(81.4,34.25) v1(81.55,19.45) v1(81.6,88.47) v1(81.6,87.62) v1(81.6,86.78) v1(81.65,71.1) v1(81.65,70.25) v1(81.65,69.4) v1(81.65,68.55) v1(81.65,50.1) v1(82,85.92) v1(82,85.08) v1(82,84.22) v1(82,83.38) v1(82,18.55) v1(82,17.7) v1(82,16.85) v1(82,16) v1(82,15.15) v1(82.45,88.47) v1(82.45,87.62) v1(82.45,86.78) v1(82.5,71.1) v1(82.5,70.25) v1(82.5,69.4) v1(82.5,68.55) v1(82.85,85.92) v1(82.85,85.08) v1(82.85,84.22) v1(82.85,83.38) v1(82.85,18.55) v1(82.85,17.7) v1(82.85,16.85) v1(82.85,16) v1(82.85,15.15) v1(83.05,67.75) v1(83.05,66.9) v1(83.05,66.05) v1(83.05,65.2) v1(83.05,64.35) v1(83,40.45) v1(83,39.6) v1(83,38.75) v1(83,37.9) v1(83,37.05) v1(83,36.2) v1(83,35.35) v1(83,34.5) v1(83,33.65) v1(83.3,88.47) v1(83.3,87.62) v1(83.3,86.78) v1(83.35,71.1) v1(83.35,70.25) v1(83.35,69.4) v1(83.35,68.55) v1(83.4,72.85) v1(83.5,50.05) v1(83.7,85.92) v1(83.7,85.08) v1(83.7,84.22) v1(83.7,83.38) v1(83.7,18.55) v1(83.7,17.7) v1(83.7,16.85) v1(83.7,16) v1(83.7,15.15) v1(83.85,40.45) v1(83.85,39.6) v1(83.85,38.75) v1(83.85,37.9) v1(83.85,37.05) v1(83.85,36.2) v1(83.85,35.35) v1(83.85,34.5) v1(83.85,33.65) v1(83.9,67.75) v1(83.9,66.9) v1(83.9,66.05) v1(83.9,65.2) v1(83.9,64.35) v1(84,108.6) v1(84,104) v1(84.05,99.7) v1(83.95,19.45) v1(84,11.1) v1(84,6.3) v1(84,1.4) v1(84.15,86.78) v1(84.2,71.1) v1(84.2,70.25) v1(84.2,69.4) v1(84.2,68.55) v1(84.55,85.92) v1(84.55,85.08) v1(84.55,84.22) v1(84.5,20.3) v1(84.55,18.55) v1(84.55,17.7) v1(84.55,16.85) v1(84.55,16) v1(84.55,15.15) v1(84.7,40.45) v1(84.7,39.6) v1(84.7,38.75) v1(84.7,37.9) v1(84.7,37.05) v1(84.7,36.2) v1(84.7,35.35) v1(84.7,34.5) v1(84.7,33.65) v1(84.75,67.75) v1(84.75,66.9) v1(84.75,66.05) v1(84.75,65.2) v1(84.75,64.35) v1(84.8,19.45) v1(85,86.78) v1(85.05,71.1) v1(85.05,70.25) v1(85.05,69.4) v1(85.05,68.55) v1(85.35,20.3) v1(85.4,85.92) v1(85.4,85.08) v1(85.4,18.55) v1(85.4,17.7) v1(85.4,16.85) v1(85.4,16) v1(85.55,40.45) v1(85.55,39.6) v1(85.55,38.75) v1(85.55,37.9) v1(85.55,37.05) v1(85.55,36.2) v1(85.55,35.35) v1(85.55,34.5) v1(85.55,33.65) v1(85.6,67.75) v1(85.6,66.9) v1(85.6,66.05) v1(85.6,65.2) v1(85.6,64.35) v1(85.65,19.45) v1(85.8,92.65) v1(85.8,91.8) v1(85.8,89.25) v1(85.8,88.4) v1(85.8,82.05) v1(85.8,81.2) v1(85.8,80.35) v1(85.8,79.5) v1(85.9,71.1) v1(85.9,70.25) v1(85.9,69.4) v1(85.9,68.55) v1(86.2,20.3) v1(86.4,40.35) v1(86.4,39.5) v1(86.65,92.65) v1(86.65,91.8) v1(86.65,89.25) v1(86.65,88.4) v1(86.65,82.05) v1(86.65,81.2) v1(86.65,80.35) v1(86.65,79.5) v1(86.85,65.2) v1(86.85,64.35) v1(87,68.6) v1(87,67.75) v1(87,66.9) v1(86.95,66.05) v1(87.1,78.75) v1(87.1,77.85) v1(87.1,70.55) v1(87.15,90.95) v1(87.15,90.1) v1(87.25,40.35) v1(87.25,39.5) v1(87.25,20.4) v1(87.5,92.65) v1(87.5,91.8) v1(87.5,89.25) v1(87.5,88.4) v1(87.5,82.05) v1(87.5,81.2) v1(87.5,80.35) v1(87.5,79.5) v1(87.45,50.05) v1(87.5,43.95) v1(87.45,18.6) v1(87.45,17.75) v1(87.85,68.35) v1(87.85,67.5) v1(87.85,66.65) v1(88,90.95) v1(88,90.1) v1(87.95,78.75) v1(87.95,77.85) v1(88.1,19.5) v1(88.35,92.65) v1(88.35,91.8) v1(88.35,89.25) v1(88.35,88.4) v1(88.35,82.05) v1(88.35,81.2) v1(88.35,80.35) v1(88.35,79.5) v1(88.3,18.6) v1(88.3,17.75) v1(88.3,16.9) v1(88.7,68.35) v1(88.7,67.5) v1(88.7,66.65) v1(88.85,90.95) v1(88.85,90.1) v1(88.8,78.75) v1(88.8,77.85) v1(89.2,108.6) v1(89.2,104) v1(89.2,92.65) v1(89.2,91.8) v1(89.2,89.25) v1(89.2,88.4) v1(89.2,82.05) v1(89.2,81.2) v1(89.2,80.35) v1(89.2,79.5) v1(89.15,17.75) v1(89.15,16.9) v1(89.15,16.05) v1(89.2,11.4) v1(89.2,6.3) v1(89.2,1.4) v1(89.5,99.7) v1(89.55,68.35) v1(89.55,67.5) v1(89.55,66.65) v1(89.7,90.95) v1(89.7,90.1) v1(89.65,78.75) v1(89.65,77.85) v1(89.65,72.85) v1(90.05,92.65) v1(90.05,91.8) v1(90.05,89.25) v1(90.05,88.4) v1(90.05,82.05) v1(90.05,81.2) v1(90.05,80.35) v1(90.05,79.5) v1(90,17.75) v1(90,16.9) v1(90,16.05) v1(90.4,68.35) v1(90.4,67.5) v1(90.4,66.65) v1(90.55,90.95) v1(90.55,90.1) v1(90.5,78.75) v1(90.5,77.85) v1(90.85,17.75) v1(90.85,16.9) v1(90.85,16.05) v1(90.9,92.65) v1(90.9,91.8) v1(90.9,89.25) v1(90.9,88.4) v1(90.9,82.05) v1(90.9,81.2) v1(90.9,80.35) v1(90.9,79.5) v1(91.25,68.35) v1(91.25,67.5) v1(91.25,66.65) v1(91.35,78.75) v1(91.35,77.85) v1(91.4,90.95) v1(91.4,90.1) v1(91.7,18.6) v1(91.7,17.75) v1(91.7,16.9) v1(91.9,19.5) v1(92.1,68.35) v1(92.1,67.5) v1(92.1,66.65) v1(92.55,18.6) v1(92.55,17.75) v1(92.75,20.4) v1(92.95,81.15) v1(92.95,68.35) v1(92.95,67.5) v1(92.95,66.65) v1(93.7,70.55) v1(93.8,68.35) v1(93.8,67.5) v1(93.8,66.65) v1(94,79.8) v1(94.4,108.6) v1(94.4,16.65) v1(94.4,11.4) v1(94.4,6.3) v1(94.4,1.4) v1(94.45,104) v1(94.45,99.5) v1(94.65,68.35) v1(94.65,67.5) v1(94.65,66.65) v1(95.55,72.85) v1(95.5,68.35) v1(95.5,67.5) v1(95.5,66.65) v1(96.35,68.35) v1(96.35,67.5) v1(96.35,66.65) v1(97.2,68.35) v1(97.2,67.5) v1(97.2,66.65) v1(98.05,68.35) v1(98.05,67.5) v1(98.05,66.65) v1(98.28,90.12) v1(98.8,99.15) v1(98.85,95.4) v1(98.9,68.35) v1(98.9,67.5) v1(98.9,66.65) v1(99.5,90.45) v1(99.6,20.85) v1(99.6,16.65) v1(99.6,11.4) v1(99.65,65.8) v1(99.65,64.95) v1(99.65,64.1) v1(99.8,108.6) v1(99.8,71.45) v1(99.75,68.35) v1(99.75,67.5) v1(99.75,66.65) v1(99.75,61) v1(99.75,55.65) v1(99.75,50.3) v1(99.75,44.95) v1(99.75,39.3) v1(99.8,1.4) v1(100.2,103.8) v1(100.2,6.2) v1(100.4,76.25) v1(100.5,65.8) v1(100.5,64.95) v1(100.5,64.1) v1(100.6,68.35) v1(100.6,67.5) v1(100.6,66.65) v1(101.15,88.8) v1(101.75,84.65) v1(102.1,37.5) v1(102.1,32) v1(102.1,26.5) v1(102.35,81.25) v1(103.05,94.7) v1(103.1,89.45) v1(103.2,83.8) v1(103.2,79.05) v1(103.2,73.75) v1(103.2,68.45) v1(103.2,63.2) v1(103.2,57.95) v1(103.2,52.7) v1(103.2,47.45) v1(103.25,41.5) v1(103.5,86.35) v1(103.8,100.2) v1(103.8,9.8) v1(104.35,36.95) v1(104.35,31.7) v1(104.35,26.45) v1(104.35,21.55) v1(104.45,16.65) v1(104.45,11.45) v1(105.1,40.65) v1(105.2,82.8) v1(105.2,78.25) v1(105.2,73.05) v1(105.2,67.75) v1(105.2,62.55) v1(105.2,57.3) v1(105.2,51.95) v1(105.2,46.75) v1(108.6,99.8) v1(108.6,94.7) v1(108.6,89.45) v1(108.6,84.2) v1(108.6,78.95) v1(108.6,73.7) v1(108.6,68.45) v1(108.6,63.2) v1(108.6,57.95) v1(108.6,52.7) v1(108.6,47.45) v1(108.6,42.2) v1(108.6,36.95) v1(108.6,31.7) v1(108.6,26.45) v1(108.6,21.2) v1(108.6,15.95) v1(108.6,10.2)
P-GND: length 121.1
  TOP w0.3: 42.5,22.65 42.1,22.65 42,22.55 41.35,22.55 C34.2 40.1,22.35 ; IC5.3 51.19,34.75 ; IC5.3 51.19,37 ; IC5.3 50.05,35.87 ; IC5.3 52.3,35.87 ; 31.5,85.85 C7.1 29.4,85.85 ; J1.2 15.95,15.4 ; J1.2 14.7,16.68 ; J1.2 17.25,16.68 ; J1.2 15.95,17.9 ; R33.2 19.1,71.45 ; R33.2 20.7,71.45 ; R33.2 v1(19.9,72.35) ; 21.3,67.45 R34.2 v1(20.4,68.25) ; R42.1 50,26.85 ; R42.1 49.2,27.75 ; R42.1 48.4,26.85 ; 47.55,26.85 C33.2 47.55,28.95 ; C32.1 26.05,71.03 ; C32.1 27.35,71.03 ; C32.1 v1(26.7,71.8) ; Q8.S 30.3,69.9 ; 26.15,66.95 26.15,67.1 26.1,67.15 26.1,67.5 26.05,67.55 ; IC2.6 35.6,14.28 35.6,15.29 35.55,15.34 35.55,16.2 v1(35.75,16.4) ; IC6.3 51.19,25.62 ; IC6.3 51.19,27.92 ; IC6.3 52.34,26.77 ; IC6.3 50.04,26.77 ; TP1.1 26,6.8 ; TP1.1 24.8,8 ; TP1.1 27.2,8 ; TP1.1 26,9.2 ; 43.5,22.85 R44.1 42.7,22.05 ; D3.1 v1(34.55,74.65) ; C35.2 26.8,68 ; 25.4,65.6 R39.1 v1(26.35,66.4)
  TOP w0.4: IC2.10 34.98,9.88
  TOP w0.5: Q8.S v1(29.45,70.85) ; C34.2 v1(41.15,21.45) ; IC4.5 v1(48.05,26.15) ; C33.2 v1(48.45,27.9) ; v1(30.45,84.95) C7.1 ; D3.1 33.55,75.6 ; C39.2 v1(31.85,68.8) ; C8.2 33.65,41.9
  TOP w0.6: 23.98,74.1 23.98,76.5 24.3,76.81 C31.2 ; 27.39,81.03 IC1.7 27.39,83.78
  TOP w0.7: C31.2 v1(24.3,78.7)
  CONDUCTIVE2 w0.3: IC5.3 52.34,35.87 ; IC5.3 50.04,35.87 ; IC5.3 51.19,37.02 ; IC5.3 51.19,34.72 ; IC6.3 51.19,27.92 ; IC6.3 51.19,25.62 ; IC6.3 52.34,26.77 ; IC6.3 50.04,26.77 ; J1.2 15.95,15.4 ; J1.2 17.25,16.68 ; J1.2 15.95,17.93 ; J1.2 14.7,16.68 ; TP1.1 26,6.8 ; TP1.1 26,9.2 ; TP1.1 24.8,8 ; TP1.1 27.2,8
  CONDUCTIVE3 w0.3: J1.2 14.7,16.68 ; J1.2 17.2,16.68 ; J1.2 15.95,15.35 ; J1.2 15.95,17.93 ; IC5.3 51.19,34.72 ; IC5.3 51.19,37.02 ; IC5.3 50.04,35.87 ; IC5.3 52.34,35.87 ; TP1.1 24.8,8 ; TP1.1 26,9.2 ; TP1.1 27.2,8 ; TP1.1 26,6.8 ; IC6.3 52.34,26.77 ; IC6.3 51.19,27.92 ; IC6.3 50.04,26.77 ; IC6.3 51.19,25.62
  BOTTOM w0.3: IC5.3 51.19,34.75 ; IC5.3 52.3,35.87 ; IC5.3 50.1,35.87 ; IC5.3 51.19,37 ; 26.02,67.25 26.02,67.95 v1(26.8,67.95) 26.65,68.1 26.65,69.1 ; 26.5,69.9 R35.1 26.65,69.1 ; 26.65,69.1 27.25,69.1 ; IC6.3 52.34,26.77 ; IC6.3 51.19,25.62 ; IC6.3 50.04,26.77 ; IC6.3 51.19,27.92 ; TP1.1 24.8,8 ; TP1.1 26,9.2 ; TP1.1 27.2,8 ; TP1.1 26,6.8 ; J1.2 15.95,17.93 ; J1.2 17.2,16.68 ; J1.2 14.7,16.68 ; J1.2 15.95,15.43
  vias: v1(1.4,99.8) v1(1.4,94.7) v1(1.4,89.45) v1(1.4,84.2) v1(1.4,78.95) v1(1.4,73.7) v1(1.4,68.45) v1(1.4,63.2) v1(1.4,57.95) v1(1.4,52.7) v1(1.4,47.45) v1(1.4,42.2) v1(1.4,36.95) v1(1.4,31.7) v1(1.4,26.45) v1(1.4,21.2) v1(1.4,15.95) v1(1.4,10.2) v1(2.15,92.7) v1(2.15,87.4) v1(2.15,82.1) v1(2.15,76.8) v1(2.15,71.5) v1(2.15,66.2) v1(2.15,60.9) v1(2.15,55.6) v1(2.15,50.3) v1(3.2,29.2) v1(3.8,44.9) v1(3.8,34) v1(3.85,39.45) v1(3.9,23.1) v1(6.2,100.2) v1(6.2,97.15) v1(6.2,9.8) v1(6.7,20.75) v1(6.8,15.85) v1(9.8,103.8) v1(9.8,6.2) v1(10.2,108.6) v1(10.2,1.4) v1(10.75,101.7) v1(10.75,20.75) v1(12,5.45) v1(12.1,10.55) v1(12.15,15.85) v1(14.7,19.95) v1(14.7,18.45) v1(14.85,105.8) v1(15.6,108.6) v1(15.6,1.4) v1(16.4,20.75) v1(17.3,69.5) v1(17.3,64.15) v1(17.3,59) v1(17.3,54.25) v1(17.35,88.2) v1(17.35,82) v1(17.35,75.25) v1(17.35,52) v1(17.45,19.35) v1(17.8,41.75) v1(17.8,37.1) v1(17.8,5.45) v1(17.9,14.8) v1(17.9,10.55) v1(18.05,48.05) v1(18.05,45.8) v1(19.65,77.75) v1(19.6,74.3) v1(19.65,63.5) v1(19.65,59.05) v1(19.65,54.45) v1(20.2,50.5) v1(20.35,83.95) v1(20.55,75.25) v1(20.8,108.6) v1(20.8,1.4) v1(21.25,107.35) v1(21.2,80.7) v1(21.7,89.75) v1(21.7,66.95) v1(21.85,45.8) v1(22.05,19.35) v1(22.25,93.15) v1(22.55,63.8) v1(22.75,86.65) v1(22.85,47.85) v1(22.95,18.25) v1(22.95,17.4) v1(22.95,16.55) v1(22.95,15.7) v1(22.95,14.85) v1(22.95,14) v1(22.95,13.15) v1(22.95,12.3) v1(23,41.75) v1(23,37.1) v1(23.1,20.85) v1(23.3,50.75) v1(23.4,71.4) v1(23.5,93.2) v1(23.6,5.45) v1(23.7,64.7) v1(23.7,10.55) v1(23.75,83.9) v1(23.8,18.25) v1(23.8,17.4) v1(23.8,16.55) v1(23.8,15.7) v1(23.8,14.85) v1(23.8,14) v1(23.8,13.15) v1(23.8,12.3) v1(24,74.12) v1(24.65,18.25) v1(24.65,17.4) v1(24.65,16.55) v1(24.65,15.7) v1(24.65,14.85) v1(24.65,14) v1(24.65,13.15) v1(24.65,12.3) v1(24.95,63.05) v1(25.05,58.8) v1(25.05,54.55) v1(25.2,80.3) v1(25.5,18.25) v1(25.5,17.4) v1(25.5,16.55) v1(25.5,15.7) v1(25.5,14.85) v1(25.5,14) v1(25.5,13.15) v1(25.5,12.3) v1(25.85,41.8) v1(26,108.6) v1(26,1.4) v1(26.15,76.25) v1(26.25,86.4) v1(26.45,44.3) v1(26.35,18.25) v1(26.35,17.4) v1(26.35,16.55) v1(26.35,15.7) v1(26.35,14.85) v1(26.35,14) v1(26.35,13.15) v1(26.35,12.3) v1(26.6,65.15) v1(27,107.35) v1(27.11,24.43) v1(27.2,18.25) v1(27.2,17.4) v1(27.2,16.55) v1(27.2,15.7) v1(27.2,14.85) v1(27.2,14) v1(27.2,13.15) v1(27.3,46.75) v1(27.4,81.03) v1(27.35,78.05) v1(27.55,22.8) v1(28,58.8) v1(28,54.55) v1(28,49.9) v1(28.05,75.2) v1(28.1,63.05) v1(28.05,17.95) v1(28.05,14.85) v1(28.05,14) v1(28.2,37.1) v1(29.1,90) v1(29.05,65.5) v1(29.2,85.95) v1(29.35,5.3) v1(29.65,77.17) v1(29.6,10.55) v1(29.7,41.05) v1(29.7,25.85) v1(30.15,81.78) v1(30.05,44.05) v1(30.4,38.7) v1(30.5,68.35) v1(30.75,73.4) v1(30.82,32.5) v1(30.75,28.05) v1(31.2,108.6) v1(31.2,1.4) v1(31.45,61.25) v1(31.45,56.75) v1(31.45,33.75) v1(31.7,86.25) v1(31.75,66.3) v1(31.9,30.5) v1(31.95,25.85) v1(31.85,9.45) v1(32,45.85) v1(32.1,19.65) v1(32.1,18.6) v1(32.1,17.75) v1(32.3,12.2) v1(32.3,11.35) v1(32.3,10.5) v1(32.75,107.35) v1(32.75,9.45) v1(32.85,13.8) v1(33,51.8) v1(33,50.9) v1(33.15,76.1) v1(33.2,93.2) v1(33.45,15.5) v1(33.5,3.1) v1(33.65,41.65) v1(33.9,84.1) v1(33.85,52.7) v1(33.85,51.8) v1(33.85,50.9) v1(33.95,81.7) v1(34.1,71.65) v1(34.15,30.2) v1(34.15,28.1) v1(34.15,23.75) v1(34.27,87.78) v1(34.3,19.65) v1(34.7,52.7) v1(34.7,51.8) v1(34.7,50.9) v1(34.75,33.75) v1(35.4,92.65) v1(35.35,79.35) v1(35.45,61.25) v1(35.45,56.75) v1(35.55,52.7) v1(35.55,51.8) v1(35.55,50.9) v1(35.5,43.15) v1(35.5,38.9) v1(35.45,3.25) v1(35.7,35.3) v1(35.75,107.9) v1(35.75,107.05) v1(35.75,86) v1(36,24.8) v1(36.02,19.62) v1(36.1,90.3) v1(36.15,78.55) v1(36.15,77.7) v1(36.15,76.85) v1(36.2,108.65) v1(36.3,79.35) v1(36.4,52.7) v1(36.4,51.8) v1(36.4,50.9) v1(36.4,1.4) v1(36.45,81.7) v1(36.6,107.9) v1(36.6,107.05) v1(36.6,106.2) v1(36.7,76) v1(37,78.55) v1(37,77.7) v1(37,76.85) v1(37.15,79.35) v1(37.25,52.7) v1(37.25,51.8) v1(37.25,50.9) v1(37.2,31.35) v1(37.45,107.9) v1(37.45,107.05) v1(37.45,106.2) v1(37.55,76) v1(37.55,75.15) v1(37.45,36.2) v1(37.55,26.35) v1(37.65,44.85) v1(37.6,41.05) v1(37.58,20.8) v1(37.85,78.55) v1(37.85,77.7) v1(37.85,76.85) v1(38,79.35) v1(38.05,32.6) v1(38.05,29) v1(38.1,52.7) v1(38.1,51.8) v1(38.1,50.9) v1(38.3,107.9) v1(38.3,107.05) v1(38.3,106.2) v1(38.4,76) v1(38.7,78.55) v1(38.7,77.7) v1(38.7,76.85) v1(38.85,79.35) v1(38.95,52.7) v1(38.95,51.8) v1(38.95,50.9) v1(39.15,107.9) v1(39.15,107.05) v1(39.15,106.2) v1(39.2,24.2) v1(39.55,78.55) v1(39.55,77.7) v1(39.55,76.85) v1(39.45,61.25) v1(39.45,56.75) v1(39.55,35.7) v1(39.55,29.3) v1(39.7,79.35) v1(39.8,52.7) v1(39.8,51.8) v1(39.8,50.9) v1(39.8,38.85) v1(39.85,6.7) v1(39.85,5.9) v1(40,107.9) v1(40,107.05) v1(40,106.2) v1(40.2,4.8) v1(40.4,78.55) v1(40.4,77.7) v1(40.4,76.85) v1(40.65,52.7) v1(40.65,51.8) v1(40.65,50.9) v1(40.65,6.7) v1(40.65,5.9) v1(40.85,107.9) v1(40.85,107.05) v1(40.85,106.2) v1(40.95,41.55) v1(41.05,3.3) v1(41.25,78.55) v1(41.25,77.7) v1(41.25,76.85) v1(41.3,108.65) v1(41.5,52.7) v1(41.5,51.8) v1(41.5,50.9) v1(41.6,1.4) v1(41.7,107.9) v1(41.7,107.05) v1(41.7,106.2) v1(41.8,79.9) v1(41.95,35.95) v1(41.95,30.3) v1(42,20.9) v1(42.1,78.55) v1(42.1,77.7) v1(42.1,76.85) v1(42.35,52.7) v1(42.35,51.8) v1(42.35,50.9) v1(42.55,107.9) v1(42.55,107.05) v1(42.55,106.2) v1(42.45,79.35) v1(42.85,80.1) v1(42.95,105.35) v1(42.95,78.55) v1(42.95,77.7) v1(42.95,76.85) v1(43.2,52.7) v1(43.2,51.8) v1(43.2,50.9) v1(43.3,80.85) v1(43.3,79.35) v1(43.4,107.9) v1(43.4,107.05) v1(43.4,106.2) v1(43.45,61.25) v1(43.45,56.75) v1(43.45,36.85) v1(43.45,30.3) v1(43.65,23.15) v1(43.7,80.1) v1(43.8,105.35) v1(43.8,78.55) v1(43.8,77.7) v1(43.8,76.85) v1(44.05,52.7) v1(44.05,51.8) v1(44.05,50.9) v1(44.15,80.85) v1(44.15,79.35) v1(44.25,107.9) v1(44.25,107.05) v1(44.25,106.2) v1(44.2,27.1) v1(44.55,80.1) v1(44.55,3.6) v1(44.65,78.55) v1(44.65,77.7) v1(44.65,76.85) v1(44.7,105.35) v1(44.9,52.7) v1(44.9,51.8) v1(44.9,50.9) v1(44.85,37.65) v1(44.9,6.5) v1(45,80.85) v1(45,79.35) v1(45.1,107.05) v1(45.1,106.2) v1(45.5,78.55) v1(45.5,77.7) v1(45.5,76.85) v1(45.75,52.7) v1(45.75,51.8) v1(45.75,50.9) v1(45.9,20.9) v1(46.35,78.55) v1(46.35,77.7) v1(46.35,76.85) v1(46.6,51.8) v1(46.6,50.9) v1(46.7,29.15) v1(46.8,108.6) v1(46.8,42.8) v1(46.8,1.4) v1(46.85,23.35) v1(47.2,78.55) v1(47.2,77.7) v1(47.2,76.85) v1(47.35,82.65) v1(47.45,61.25) v1(47.45,56.75) v1(47.45,32.75) v1(47.5,9.1) v1(47.65,87.25) v1(47.65,79.35) v1(47.6,76.05) v1(47.7,66.5) v1(47.75,91.3) v1(47.75,90.45) v1(47.8,71.7) v1(47.9,105.05) v1(47.85,49.6) v1(47.85,48.75) v1(47.85,47.9) v1(47.85,47.05) v1(48.05,78.55) v1(48.05,77.7) v1(48.05,76.85) v1(48.45,34.05) v1(48.6,93) v1(48.6,92.15) v1(48.6,91.3) v1(48.6,90.45) v1(48.6,6.7) v1(48.75,105.05) v1(48.75,49.6) v1(48.75,48.75) v1(48.75,47.9) v1(48.75,47.05) v1(49.05,21.95) v1(49.15,53.05) v1(49.2,36.35) v1(49.25,27.75) v1(49.5,18.9) v1(49.6,105.65) v1(49.6,104.8) v1(49.6,103.95) v1(49.6,103.1) v1(49.6,102.25) v1(49.6,101.4) v1(49.6,100.55) v1(49.6,99.7) v1(49.6,98.85) v1(49.6,98) v1(49.6,97.15) v1(49.6,96.3) v1(49.6,95.45) v1(49.6,94.6) v1(49.6,93.75) v1(49.6,92.9) v1(49.6,92.05) v1(49.6,91.2) v1(49.6,90.35) v1(49.95,74.4) v1(49.95,69.1) v1(49.95,63.8) v1(50.2,23.3) v1(50.45,105.65) v1(50.45,104.8) v1(50.45,103.95) v1(50.45,103.1) v1(50.45,102.25) v1(50.45,101.4) v1(50.45,100.55) v1(50.45,99.7) v1(50.45,98.85) v1(50.45,98) v1(50.45,97.15) v1(50.45,96.3) v1(50.45,95.45) v1(50.45,94.6) v1(50.45,93.75) v1(50.45,92.9) v1(50.45,92.05) v1(50.45,91.2) v1(50.45,90.35) v1(50.7,60.15) v1(50.7,59.3) v1(50.7,58.45) v1(50.7,57.6) v1(50.7,56.75) v1(50.7,55.9) v1(51.3,105.65) v1(51.3,104.8) v1(51.3,103.95) v1(51.3,103.1) v1(51.3,102.25) v1(51.3,101.4) v1(51.3,100.55) v1(51.3,99.7) v1(51.3,98.85) v1(51.3,98) v1(51.3,97.15) v1(51.3,96.3) v1(51.3,95.45) v1(51.3,94.6) v1(51.3,93.75) v1(51.3,92.9) v1(51.3,92.05) v1(51.3,91.2) v1(51.3,90.35) v1(51.55,60.15) v1(51.55,59.3) v1(51.55,58.45) v1(51.55,57.6) v1(51.55,56.75) v1(51.55,55.9) v1(52,108.5) v1(52,1.5) v1(52.1,103.25) v1(52.1,98) v1(52.1,92.75) v1(52.1,87.5) v1(52.1,82.25) v1(52.1,77) v1(52.1,71.75) v1(52.1,66.5) v1(52.1,61.25) v1(52.1,55) v1(52.1,53.3) v1(52.1,48.05) v1(52.1,42.8) v1(52.1,37.55) v1(52.1,32.3) v1(52.1,27.8) v1(52.1,22.55) v1(52.1,17.4) v1(52.1,12.1) v1(52.1,6.8) v2(27.4,83.78) v3(34.65,12.85) v3(34.65,11.82) v3(34.65,10.88) v3(34.65,9.85) v3(35.65,12.85) v3(35.65,11.82) v3(35.65,10.88) v3(35.65,9.85) v3(36.6,12.85) v3(36.6,11.82) v3(36.6,10.88) v3(36.6,9.85) v3(37.55,12.85) v3(37.55,11.82) v3(37.55,10.88) v3(37.55,9.85) v3(38.55,12.85) v3(38.55,11.82) v3(38.55,10.88) v3(38.55,9.85)
VOUT: length 67.6
  TOP w0.6: v1(67.85,21.3) R71.1
  TOP w0.8: 104.2,84 104.2,41.05 100.05,36.9
  CONDUCTIVE3 w0.6: CN4.1 77.22,31.62 76.45,30.85 76.45,28.27 69.48,21.3 v1(67.85,21.3)
  vias: v1(78.45,29.4) v1(78.45,28.55) v1(78.45,27.7) v1(78.45,26.85) v1(78.45,26) v1(78.45,25.15) v1(79.3,29.4) v1(79.3,28.55) v1(79.3,27.7) v1(79.3,26.85) v1(79.3,26) v1(79.3,25.15) v1(80.15,29.4) v1(80.15,28.55) v1(80.15,27.7) v1(80.15,26.85) v1(80.15,26) v1(80.15,25.15) v1(81,29.6) v1(81,28.75) v1(81,27.9) v1(81,27.05) v1(81,26.2) v1(81,25.35) v1(81.05,24) v1(81.05,23.15) v1(81.05,22.3) v1(81.85,29.6) v1(81.85,28.75) v1(81.85,27.9) v1(81.85,27.05) v1(81.85,26.2) v1(81.85,25.35) v1(81.9,24) v1(81.9,23.15) v1(81.9,22.3) v1(82,31.3) v1(82,30.45) v1(82.7,29.6) v1(82.7,28.75) v1(82.7,27.9) v1(82.7,27.05) v1(82.7,26.2) v1(82.7,25.35) v1(82.85,30.45) v1(82.75,24) v1(82.75,23.15) v1(82.75,22.3) v1(83.55,29.6) v1(83.55,28.75) v1(83.55,27.9) v1(83.55,27.05) v1(83.55,26.2) v1(83.55,25.35) v1(83.6,24) v1(83.6,23.15) v1(83.6,22.3) v1(84.4,28.75) v1(84.4,27.9) v1(84.4,27.05) v1(84.4,26.2) v1(84.4,25.35) v1(84.45,24) v1(84.45,23.15) v1(84.45,22.3) v1(87.45,25.05) v1(87.45,24.2) v1(87.45,23.35) v1(88.3,25.05) v1(88.3,24.2) v1(88.3,23.35) v1(89.15,25.05) v1(89.15,24.2) v1(89.15,23.35) v1(90,25.05) v1(90,24.2) v1(90,23.35) v1(90.85,25.05) v1(90.85,24.2) v1(90.85,23.35) v1(91.15,37.25) v1(91.15,36.4) v1(91.15,35.55) v1(91.15,34.7) v1(91.15,33.85) v1(91.15,33) v1(91.15,32.15) v1(91.7,25.05) v1(91.7,24.2) v1(91.7,23.35) v1(92,37.25) v1(92,36.4) v1(92,35.55) v1(92,34.7) v1(92,33.85) v1(92,33) v1(92,32.15) v1(92.55,25.05) v1(92.55,24.2) v1(92.55,23.35) v1(92.85,37.25) v1(92.85,36.4) v1(92.85,35.55) v1(92.85,34.7) v1(92.85,33.85) v1(92.85,33) v1(92.85,32.15) v1(93.7,37.25) v1(93.7,36.4) v1(93.7,35.55) v1(93.7,34.7) v1(93.7,33.85) v1(93.7,33) v1(93.7,32.15) v1(94.55,37.25) v1(94.55,36.4) v1(94.55,35.55) v1(94.55,34.7) v1(94.55,33.85) v1(94.55,33) v1(94.55,32.15) v1(95.4,37.25) v1(95.4,36.4) v1(95.4,35.55) v1(95.4,34.7) v1(95.4,33.85) v1(95.4,33) v1(95.4,32.15) v1(96.25,37.25) v1(96.25,36.4) v1(96.25,35.55) v1(96.25,34.7) v1(96.25,33.85) v1(96.25,33) v1(96.25,32.15) v1(97.1,37.25) v1(97.1,36.4) v1(97.1,35.55) v1(97.1,34.7) v1(97.1,33.85) v1(97.1,33) v1(97.1,32.15) v1(97.95,37.25) v1(97.95,36.4) v1(97.95,35.55) v1(97.95,34.7) v1(97.95,33.85) v1(97.95,33) v1(98.8,37.25) v1(98.8,36.4) v1(98.8,35.5) v1(98.8,34.7) v1(98.8,33.85)
VSEC: length 28.1
  TOP w0.5: v1(79.9,47.2) 82.65,49.95 82.65,51.55 ; v1(70.6,37.8) R65.1
  TOP w0.8: v2(68.85,48.05) D4.1
  CONDUCTIVE3 w0.5: v1(79.9,47.2) 79.9,47.1 v1(70.6,37.8)
  CONDUCTIVE3 w1: v2(73.03,53.42) 68.85,49.25 v2(68.85,48.05)
  vias: v1(76.55,59.7) v1(76.55,58.85) v1(76.55,58) v1(76.55,57.15) v1(76.55,56.3) v1(76.55,55.45) v1(76.55,54.6) v1(76.55,53.75) v1(76.55,52.9) v1(76.55,52.05) v1(77.4,60.55) v1(77.4,59.7) v1(77.4,58.85) v1(77.4,58) v1(77.4,57.15) v1(77.4,56.3) v1(77.4,55.45) v1(77.4,54.6) v1(77.4,53.75) v1(77.4,52.9) v1(77.4,52.05) v1(77.4,51.2) v1(78.25,61.4) v1(78.25,60.55) v1(78.25,59.7) v1(78.25,58.85) v1(78.25,58) v1(78.25,57.15) v1(78.25,56.3) v1(78.25,55.45) v1(78.25,54.6) v1(78.25,53.75) v1(78.25,52.9) v1(78.25,52.05) v1(78.25,51.2) v1(79.1,61.4) v1(79.1,60.55) v1(79.1,59.7) v1(79.1,58.85) v1(79.1,58) v1(79.1,57.15) v1(79.1,56.3) v1(79.1,55.45) v1(79.1,54.6) v1(79.1,53.75) v1(79.1,52.9) v1(79.1,52.05) v1(79.1,51.2) v1(79.95,61.4) v1(79.95,60.55) v1(79.95,59.7) v1(79.95,58.85) v1(79.95,58) v1(79.95,57.15) v1(79.95,56.3) v1(79.95,55.45) v1(79.95,54.6) v1(79.95,53.75) v1(79.95,52.9) v1(79.95,52.05) v1(80.8,55.45) v1(80.8,54.6) v1(80.8,53.75) v1(80.8,52.9) v1(81.65,55.45) v1(81.65,54.6) v1(81.65,53.75)
N04422: length 28.6
  CONDUCTIVE2 w0.6: v1(17.1,46.48) v1(16.25,47.33) ; v1(17.1,46.48) v1(17.1,47.33) v1(16.25,47.33) ; v1(17.1,46.48) v1(16.25,46.48) v1(16.25,47.33)
  CONDUCTIVE2 w0.8: v2(29.95,39.95) v2(30.95,39.95)
  CONDUCTIVE3 w1: v2(30.95,39.95) v2(29.95,39.95) 29.25,39.95 22.3,46.9 16.45,46.9
  BOTTOM w0.6: v1(16.25,46.48) v1(16.25,47.33) v1(17.1,47.33) ; v1(16.25,46.48) v1(17.1,46.48) v1(17.1,47.33) ; v1(16.25,46.48) v1(17.1,47.33)
  BOTTOM w0.8: v2(29.95,39.95) v2(30.95,39.95)
  vias: v1(33.7,106.4) v1(33.7,105.55) v1(33.7,104.7) v1(33.7,103.85) v1(33.7,103) v1(33.7,102.15) v1(33.7,101.3) v1(33.7,100.45) v1(33.7,99.6) v1(33.7,98.75) v1(33.7,97.9) v1(33.7,97.05) v1(34.55,106.4) v1(34.55,105.55) v1(34.55,104.7) v1(34.55,103.85) v1(34.55,103) v1(34.55,102.15) v1(34.55,101.3) v1(34.55,100.45) v1(34.55,99.6) v1(34.55,98.75) v1(34.55,97.9) v1(34.55,97.05) v1(35.4,105.55) v1(35.4,104.7) v1(35.4,103.85) v1(35.4,103) v1(35.4,102.15) v1(35.4,101.3) v1(35.4,100.45) v1(35.4,99.6) v1(35.4,98.75) v1(35.4,97.9) v1(35.4,97.05) v1(36.3,98) v1(36.3,97.15) v1(36.3,96.3) v1(37.15,98) v1(37.15,97.15) v1(37.15,96.3) v1(37.15,95.45) v1(38,98) v1(38,97.15) v1(38,96.3) v1(38,95.45) v1(38,94.6) v1(38.85,98) v1(38.85,97.15) v1(38.85,96.3) v1(38.85,95.45) v1(38.85,94.6) v1(39.7,98) v1(39.7,97.15) v1(39.7,96.3) v1(39.7,95.45) v1(39.7,94.6) v1(40.55,98) v1(40.55,97.15) v1(40.55,96.3) v1(40.55,95.45) v1(40.55,94.6) v1(41.4,98) v1(41.4,97.15) v1(41.4,96.3) v1(41.4,95.45) v1(41.4,94.6)
N07250: length 2.7
  TOP w0.6: IC1.3 26.11,89.15
  BOTTOM w1.2: v2(26.1,89.15) 27.35,89.15
N08453:
  vias: v1(23.8,36.15) v1(23.8,35.3) v1(23.8,34.45) v1(23.8,33.6) v1(23.8,32.75) v1(23.8,31.9) v1(23.8,31.05) v1(23.8,30.2) v1(23.8,29.35) v1(23.8,28.5) v1(24.65,36.15) v1(24.65,35.3) v1(24.65,34.45) v1(24.65,33.6) v1(24.65,32.75) v1(24.65,31.9) v1(24.65,31.05) v1(24.65,30.2) v1(24.65,29.35) v1(24.65,28.5) v1(25.5,36.15) v1(25.5,35.3) v1(25.5,34.45) v1(25.5,33.6) v1(25.5,32.75) v1(25.5,31.9) v1(25.5,31.05) v1(25.5,30.2) v1(25.5,29.35) v1(25.5,28.5) v1(26.35,36.15) v1(26.35,35.3) v1(26.35,34.45) v1(26.35,33.6) v1(26.35,32.75) v1(26.35,31.9) v1(26.35,31.05) v1(26.35,30.2) v1(26.35,29.35) v1(26.35,28.5) v1(27.2,36.15) v1(27.2,35.3) v1(27.2,34.45) v1(27.2,33.6) v1(27.2,32.75) v1(27.2,31.9) v1(27.2,31.05) v1(27.2,30.2) v1(27.2,29.35) v1(27.2,28.5)
N17449: length 23.1
  TOP w0.3: 96.98,89.46 96.98,93.74 93.53,97.2 84.1,97.2 82.92,96.03 82.92,93.83
  TOP w0.6: 96.98,89.46 IC7.6
N20934: length 27.2
  TOP w0.3: 82.92,79.32 82.92,76 83.58,75.35 95.95,75.35 99.85,79.25 99.85,82.3 98.75,83.4 IC7.4
N76065: length 1.3
  TOP w0.6: D2.1 R10.1
N76205: length 1.3
  TOP w0.6: D2.2 R9.1 32.52,79.03
N143092: length 42.3
  TOP w1: v2(33.05,23.4) v2(33.05,24.5) 33.05,35.65
  CONDUCTIVE2 w0.8: v2(37.15,5) v2(38.15,5) ; v2(33.05,23.4) v2(33.05,24.5)
  CONDUCTIVE3 w0.8: v2(33.05,23.4) v2(33.05,24.5) ; v2(37.15,5) v2(38.15,5)
  BOTTOM w1: v2(33.05,24.5) v2(33.05,23.4) 33.2,23.25 33.2,16.75 30.7,14.25 30.7,8.8 31.3,8.2 33.95,8.2 v2(37.15,5) v2(38.15,5)
N146449: length 1.7
  TOP w0.3: 35.65,6.78 35.62,6.8 IC2.11
N147270: length 5.4
  TOP w0.4: IC2.3 37.58,15.25
  TOP w0.45: 37.75,19.55 37.58,19.38 37.58,15.25
N147939: length 68.2
  TOP w0.3: IC2.8 v1(34.33,15.5) ; v1(25.8,63.3) 27.35,64.85 27.35,67.25 27.5,67.4 27.5,68.8 Q8.D 26.7,69.6 26.7,70.05 IC3.4
  BOTTOM w0.3: v1(34.33,15.5) 34.33,15.97 36.77,18.43 36.77,26.68 38.8,28.7 38.8,40.95 35.85,43.9 31.2,43.9 25.8,49.3 v1(25.8,63.3)
N154702: length 6.5
  TOP w0.25: 36.27,4.45 36.27,4.17 R21.2 36.5,4.22 36.27,4.45 ; 36.27,4.45 IC2.12
  TOP w0.3: R22.1 R21.2
N156453: length 2
  TOP w0.6: IC3.8 21.45,76.66 R31.2
N156506: length 1.9
  TOP w0.6: 25.75,77.15 25.25,76.66 IC3.5
N157128: length 1.6
  TOP w0.3: 21.45,70.05 IC3.1 R33.1
N157174: length 3
  TOP w0.3: IC3.2 22.71,68.25 ; R38.1 R34.1
N157213: length 5.6
  TOP w0.3: 23.98,70.05 23.98,68.25 ; 24,68.25 C35.1 R39.2 24,65.6 v1(24.15,65.45)
  BOTTOM w0.3: v1(24.15,65.45) R36.2
N179665: length 3.4
  TOP w0.6: IC1.6 26.11,79.42 R32.1
N179711: length 5.9
  TOP w0.6: IC1.5 24.84,81.25 23.95,80.35 22.15,80.35 R31.1
N180947: length 50.2
  TOP w0.3: v1(22.7,64.7) R38.2
  BOTTOM w0.3: v1(22.7,64.7) 23.4,64 26.15,64 27.25,62.9 27.25,49.55 31.7,45.1 36.35,45.1 48.12,33.33 IC5.4
N181356: length 1.7
  TOP w0.7: 32.85,65.8 32.85,66.7 32.75,66.8 C38.2
  vias: v1(39.05,72.2) v1(39.05,71.35) v1(39.05,70.5) v1(39.9,73.05) v1(39.9,72.2) v1(39.9,71.35) v1(39.9,70.5) v1(40.75,73.9) v1(40.75,73.05) v1(40.75,72.2) v1(40.75,71.35) v1(40.75,70.5) v1(41.45,74.75) v1(41.6,73.9) v1(41.6,73.05) v1(41.6,72.2) v1(41.6,71.35) v1(41.6,70.5) v1(42.3,74.75) v1(42.4,75.6) v1(42.45,73.9) v1(42.45,73.05) v1(42.45,72.2) v1(42.45,71.35) v1(42.45,70.5) v1(43.15,74.75) v1(43.25,75.6) v1(43.3,73.9) v1(43.3,73.05) v1(43.3,72.2) v1(43.3,71.35) v1(43.3,70.5) v1(44,74.75) v1(44.1,75.6) v1(44.15,73.9) v1(44.15,73.05) v1(44.15,72.2) v1(44.15,71.35) v1(44.1,70.5) v1(44.85,74.75) v1(44.9,70.5) v1(44.95,75.6) v1(45,73.9) v1(45,73.05) v1(45,72.2) v1(45,71.35) v1(45.85,73.6) v1(45.85,72.75) v1(45.85,71.9) v1(46.7,73.6) v1(46.7,72.75) v1(46.7,71.9)
N183929: length 51.6
  TOP w0.3: IC4.1 43.6,26.15 42.9,26.85 R45.1 v1(42.7,27.75) ; 28.1,66.45 28.1,64.1 v1(26.55,62.55)
  BOTTOM w0.3: v1(42.7,27.75) 42.7,37.9 36.1,44.5 31.45,44.5 26.55,49.4 v1(26.55,62.55)
N185355: length 5.4
  TOP w0.3: R42.2 R41.1 IC4.4 ; 49.2,24.23 IC6.4
N185580: length 5.5
  TOP w0.3: IC4.3 R44.2 ; R44.2 R45.2 ; R44.2 41.3,24.25 R43.1
N188391: length 2.9
  TOP w0.3: R71.2 R72.2 IC9.3
N188419: length 47.6
  TOP w0.6: C45.2 64.1,25.5 64.5,25.1 IC9.2
  TOP w0.7: 67.1,29.5 v1(66.1,29.5) ; R62.2 C41.1 v2(60.75,29.1) ; C45.2 v2(60.6,25.5)
  TOP w1: Q7.3 TP19.1
  BOTTOM w0.8: 61.3,25.5 64,25.5 66.1,27.6 v1(66.1,29.5) ; 61.3,25.5 v2(60.6,25.5) 60.75,25.65 60.75,26.05 ; 61.3,25.5 60.75,26.05 ; 60.75,26.05 v2(60.75,29.1)
  BOTTOM w1: TP19.1 63.05,35.35 61.75,34.05 61.75,30.1 v2(60.75,29.1)
N188459: length 3
  TOP w0.3: IC9.4 D6.2 R73.1
N188511: length 1.5
  TOP w0.3: 62.05,24.2 R74.2 IC9.1
N193009: length 1.9
  TOP w0.3: R74.1 59.8,24.2 59.77,24.23 IC6.1
N197110: length 6.8
  TOP w0.3: IC5.2 59.97,35.87 60.05,35.95 R63.1 IC8.2 62.25,37.2 C43.1 62.75,39.05
N197426: length 3.1
  TOP w0.3: R63.2 R62.1 59.8,33.35 59.8,33.33 58.83,33.33
N197850: length 1.2
  TOP w0.3: R66.1 69.6,36.4
N197854: length 5.8
  TOP w0.3: R66.2 R67.2 65.5,36.55 65.5,37.65 64.15,37.65 ; IC8.1 64.15,37.65 ; 64.15,37.65 C43.2
N198958: length 1.3
  TOP w0.3: R64.1 C42.1
N206320: length 2.9
  TOP w0.7: C38.1 C39.1 R37.1
N207190: length 1.9
  TOP w0.3: 32.25,70.45 32.25,71.65 32.6,72 D3.3
N207547: length 11.5
  TOP w0.3: D3.2 30.95,74.65 TP9.1
  BOTTOM w0.3: R36.1 R35.2 25.1,69.8 26.15,70.85 27.15,70.85 TP9.1
N216469: length 3.4
  TOP w0.7: R2.2 R3.2 Q3.1
N216829: length 3.4
  TOP w0.7: C8.1 R3.1 R4.2
N216837: length 31
  TOP w0.3: J1.1 16.83,20.1 23.85,20.1 27.5,23.75 CN2.1 ; v1(36.45,36.05) 36.45,37
  BOTTOM w0.3: v1(36.45,36.05) 36.45,31.45 CN2.1
N219686: length 1.5
  TOP w0.3: Q8.G 29.45,66.55

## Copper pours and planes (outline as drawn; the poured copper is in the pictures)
12V on CONDUCTIVE3: 48.1,19.36 48.07,19.49 48,19.61 43.96,23.65 43.84,23.72 43.71,23.75 40.39,23.75 40.36,23.76 40.32,23.78 39.83,24.27 39.81,24.31 39.8,24.34 39.8,27.86 39.81,27.9 39.83,27.93 40.06,28.16 40.13,28.26 40.15,28.37 40.15,30.45 40.18,30.52 40.25,30.55 41.16,30.55 41.2,30.54 41.23,30.52 41.32,30.43 41.34,30.4 41.35,30.36 41.35,30.24 41.38,30.11 41.45,29.99 41.64,29.8 41.76,29.73 41.89,29.7 45.76,29.7 45.8,29.69 45.83,29.67 46.07,29.43 46.09,29.4 46.1,29.36 46.13,26.21 46.2,26.1 51.37,20.93 51.39,20.9 51.4,20.86 51.4,5.99 51.39,5.95 51.37,5.92 51.03,5.58 51,5.56 50.96,5.55 49.64,5.55 49.6,5.56 49.57,5.58 49.23,5.92 49.21,5.95 49.2,5.99 49.2,7.38 49.18,7.49 49.11,7.59 48.13,8.57 48.11,8.6 48.1,8.64 ; 6 cut-outs
L_GND on TOP: 57.5,52.09 57.54,52.28 57.65,52.45 57.85,52.65 58.02,52.76 58.21,52.8 67.21,52.8 67.25,52.79 67.28,52.77 71.72,48.33 71.74,48.3 71.75,48.26 71.75,36.54 71.74,36.5 71.72,36.47 69.09,33.84 69.02,33.74 69,33.63 69,16.69 68.99,16.65 68.97,16.62 68.38,16.03 68.35,16.01 68.31,16 67.04,16 67,16.01 66.97,16.03 66.5,16.5 66.5,17.12 66.46,17.26 66.36,17.36 66.22,17.4 64.97,17.4 64.84,17.36 64.74,17.26 64.7,17.12 64.7,16.5 64.23,16.03 64.2,16.01 64.16,16 58.17,16 58.01,16.03 57.88,16.12 57.62,16.38 57.53,16.51 57.5,16.67 ; 5 cut-outs
